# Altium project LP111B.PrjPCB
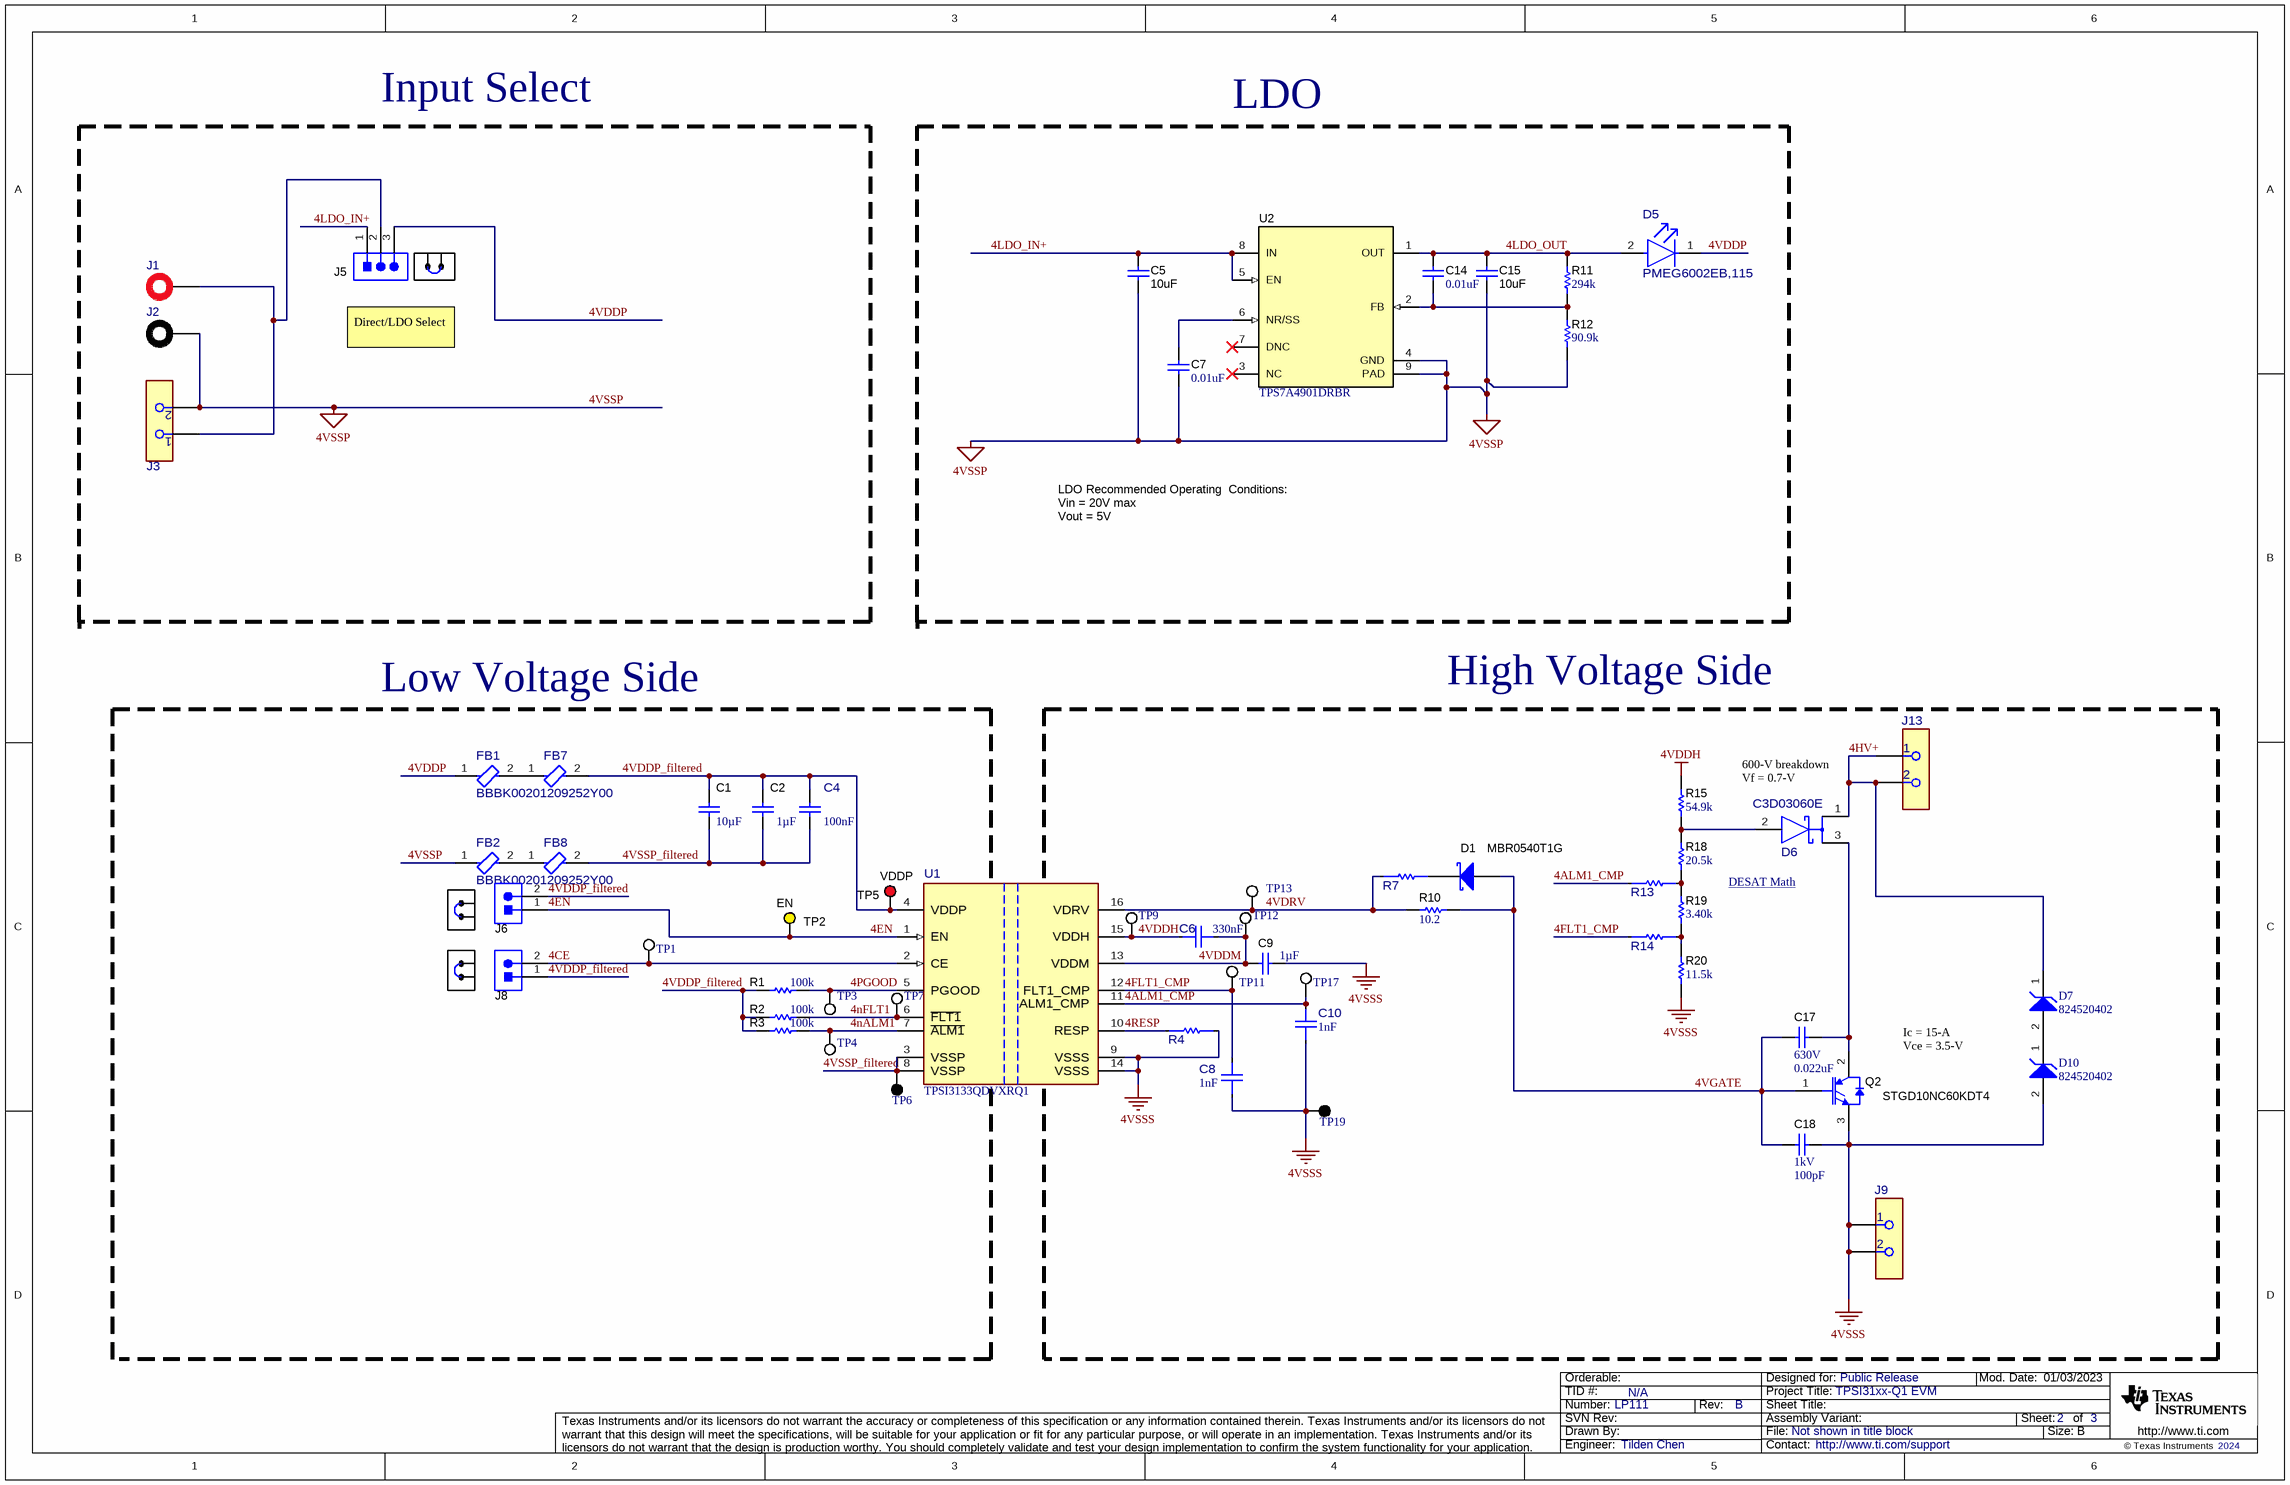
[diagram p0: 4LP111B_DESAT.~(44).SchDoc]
CopyrightYear: 2024; PCB_Layout: Tilden Chen; PCB_Rev: B; PRJ_Customer: Public Release; PRJ_Engineer: Tilden Chen; PRJ_Number: LP111; PRJ_Title: TPSI31xx-Q1 EVM; SCH_Rev: B; TechSupport: http://www.ti.com/support; TID: N/A
5 sheets, 285 parts. Net scope: global (net labels, ports and power ports of the same name join across sheets).
Board files: LP111Bv2.~(104).PcbDoc, DESAT.PcbDoc
Sheets:
  4LP111B_DESAT.~(44).SchDoc
  3LP111B_Uni-OCP_CSA.~(35).SchDoc
  2LP111B_Bi-OCP_noCSA.~(38).SchDoc
  1LP111B_Uni-OCP_noCSA.~(35).SchDoc
  LP111A_Hardware.SchDoc

## Sheet 4LP111B_DESAT.~(44).SchDoc
size 431 x 279 mm; Date: Not shown in title block; ApprovedBy: Not shown in title block; CheckedBy: Not shown in title block; Author: Not shown in title block; CompanyName: Not shown in title block; Engineer: Not shown in title block; Organization: Not shown in title block; Address1: Not shown in title block; Address2: Not shown in title block; Address3: Not shown in title block; Address4: Not shown in title block; DocumentNumber: 2; Revision: Use project parameter SCH_Rev; SheetNumber: 2; SheetTotal: 3; PageSetup: Record=PageOptions¦CenterHorizontal=True¦CenterVertical=True¦PrintScale=1.00¦XCorrection=1.00¦YCorrection=1.00¦PrintKind=0¦BorderSize=5000000¦LeftOffset=0¦BottomOffset=0¦Orientation=2¦PaperLength=1000¦PaperWidth=1000¦Scale=100¦PaperSource=15¦PrintQuality=600¦MediaType=1¦DitherType=10¦PaperKind=Letter¦PrintScaleMode=1

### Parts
C1  ValueDisplayed: 10µF  [1206_180]  (hidden comment: C1206C106J3RACAUTO)
C2  Cap_F: 1µF  [0603]  (hidden comment: GCM188R71E105KA64D)
C4  Cap_F: 100nF  [FP-C0603R104K5RAC_0603-IPC_B]  (hidden comment: C0603R104K5RAC)
C5  ValueDisplayed: 10uF  [0603]  (hidden comment: GRT188R61E106ME13D)
C6  Cap_F: 330nF  [FP-CGA3E3X7R1E334K080AB_0603-MFG]  (hidden comment: CGA3E3X7R1E334K080AB)
C7  ValueDisplayed: 0.01uF  [0402]  (hidden comment: GRM155R71E103KA01D)
C8  Cap_F: 1nF  [FP-CC0603KRX7R7BB102_0603-MFG]  (hidden comment: CC0603KRX7R7BB102)
C9  Cap_F: 1µF  [0603]  (hidden comment: GCM188R71E105KA64D)
C10  Cap_F: 1nF  [FP-CC0603KRX7R7BB102_0603-MFG]  (hidden comment: CC0603KRX7R7BB102)
C14  ValueDisplayed: 0.01uF  [0402]  (hidden comment: GRM155R71E103KA01D)
C15  ValueDisplayed: 10uF  [0603]  (hidden comment: GRT188R61E106ME13D)
C17  VDC_V: 630V  ValueDisplayed: 0.022uF  [1210_150]  (hidden comment: GRM32QR72J223KW01L)
C18  VDC_V: 1kV  ValueDisplayed: 100pF  [1206]  (hidden comment: GRM31A7U3A101JW31D)
D1  MBR0540T1G  [SOD-123]
D5  PMEG6002EB,115  [FP-PMEG6002EB,115_SOD523-MFG]
D6  C3D03060E  [FP-C3D03060E_TO-252-2-MFG]
D7  824520402  [WE-TVSP_DO-214AA_Unidirectional]
D10  824520402  [WE-TVSP_DO-214AA_Unidirectional]
FB1  BBBK00201209252Y00  [FP-BBBK00201209252Y00_0805-MFG]
FB2  BBBK00201209252Y00  [FP-BBBK00201209252Y00_0805-MFG]
FB7  BBBK00201209252Y00  [FP-BBBK00201209252Y00_0805-MFG]  (value not drawn)
FB8  BBBK00201209252Y00  [FP-BBBK00201209252Y00_0805-MFG]  (value not drawn)
J1  108-0902-001  [Cinch_108-0902-001]  (value not drawn)
J2  108-0903-001  [Cinch_108-0903-001]  (value not drawn)
J3  691250610002  [FP-691250610002_CONN_TERM_BLOCK2-MFG]  (value not drawn)
J5  PEC03SAAN  [CONN_PEC03SAAN]  (value not drawn)
J6  61300211121  [WURTH_61300211121]  (value not drawn)
J8  61300211121  [WURTH_61300211121]  (value not drawn)
J9  691250610002  [FP-691250610002_CONN_TERM_BLOCK2-MFG]  (value not drawn)
J13  691250610002  [FP-691250610002_CONN_TERM_BLOCK2-MFG]  (value not drawn)
Q2  STGD10NC60KDT4  [DPAK]
R1  ValueDisplayed: 100k  [0805_HV]  (hidden comment: ERJ-6GEYJ104V)
R2  ValueDisplayed: 100k  [0805_HV]  (hidden comment: ERJ-6GEYJ104V)
R3  ValueDisplayed: 100k  [0805_HV]  (hidden comment: ERJ-6GEYJ104V)
R4  WSL060300000ZEA9  [FP-WSL060300000ZEA9_0603-MFG]  (value not drawn)
R7  WSL060300000ZEA9  [FP-WSL060300000ZEA9_0603-MFG]  (value not drawn)
R10  ValueDisplayed: 10.2  [0805_HV]  (hidden comment: CRCW080510R2FKEA)
R11  ValueDisplayed: 294k  [0402]  (hidden comment: ERJ-2RKF2943X)
R12  ValueDisplayed: 90.9k  [0402]  (hidden comment: ERJ-2RKF9092X)
R13  WSL060300000ZEA9  [FP-WSL060300000ZEA9_0603-MFG]  (value not drawn)
R14  WSL060300000ZEA9  [FP-WSL060300000ZEA9_0603-MFG]  (value not drawn)
R15  ValueDisplayed: 54.9k  [0603]  (hidden comment: CRCW060354K9FKEA)
R18  ValueDisplayed: 20.5k  [0603]  (hidden comment: CRCW060320K5FKEA)
R19  ValueDisplayed: 3.40k  [0603]  (hidden comment: M55342K12B3E40T)
R20  ValueDisplayed: 11.5k  [0805_HV]  (hidden comment: ERJ-6ENF1152V)
SH-J1  SNT-100-BK-G  [SNT-100-BK-G]  (value not drawn)
SH-J2  SNT-100-BK-G  [SNT-100-BK-G]  (value not drawn)
SH-J3  SNT-100-BK-G  [SNT-100-BK-G]  (value not drawn)
TP1  5012  [KSTN-5012_V]  (value not drawn)
TP2  EN  [Keystone5014]
TP3  5012  [KSTN-5012_V]  (value not drawn)
TP4  5012  [KSTN-5012_V]  (value not drawn)
TP5  VDDP  [Keystone5010]
TP6  5011  [Keystone5011]  (value not drawn)
TP7  5012  [KSTN-5012_V]  (value not drawn)
TP9  5012  [KSTN-5012_V]  (value not drawn)
TP11  5012  [KSTN-5012_V]  (value not drawn)
TP12  5012  [KSTN-5012_V]  (value not drawn)
TP13  5012  [KSTN-5012_V]  (value not drawn)
TP17  5012  [KSTN-5012_V]  (value not drawn)
TP19  5011  [Keystone5011]  (value not drawn)
U1  TPSI3133QDVXRQ1  [DVX0016A-MFG]
U2  TPS7A4901DRBR  [DRB0008A]

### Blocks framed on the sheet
High Voltage Side: C6 C8-C10 C17 C18 D1 D6 D7 D10 J9 J13 Q2 R4 R7 R10 R13-R15 R18-R20 TP9 TP11-TP13 TP17 TP19

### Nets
4VDDH: C6.1 R15.2 TP9.1 U1.15(VDDH)
4VSSP: C5.2 C7.2 C15.2 FB2.1 J2.1 J3.2 R12.1 U2.4(GND) U2.9(PAD)
4VSSS: C8.1 C9.1 C10.1 C18.1 D10.2(A) J9.1 J9.2 Q2.3(E) R4.2 R20.1 TP19.1 U1.9(VSSS) U1.14(VSSS)
4ALM1_CMP: C10.2 R13.1 TP17.1 U1.11(ALM1_CMP)
4CE: J8.2 TP1.1 U1.2(CE)
4EN: J6.1 TP2.1 U1.1(EN)
4FLT1_CMP: C8.2 R14.1 TP11.1 U1.12(FLT1_CMP)
4HV+: D6.1(CATHODE) D7.1(K) J13.1 J13.2
4LDO_IN+: C5.1 J5.1 U2.5(EN) U2.8(IN)
4LDO_OUT: C14.1 C15.1 D5.2(ANODE) R11.2 U2.1(OUT)
4nALM1: R3.2 TP4.1 U1.7(~{ALM1})
4nFLT1: R2.2 TP7.1 U1.6(~{FLT1})
4PGOOD: R1.2 TP3.1 U1.5(PGOOD)
4RESP: R4.1 U1.10(RESP)
4VDDM: C6.2 C9.2 TP12.1 U1.13(VDDM)
4VDDP: D5.1(CATHODE) FB1.1 J5.3
4VDDP_filtered: C1.1 C2.1 C4.2 FB7.2 J6.2 J8.1 R1.1 R2.1 R3.1 TP5.1 U1.4(VDDP)
4VDRV: R7.1 R10.1 TP13.1 U1.16(VDRV)
4VGATE: C17.2 C18.2 D1.2(A) Q2.1(G) R10.2
4VSSP_filtered: C1.2 C2.2 C4.1 FB8.2 TP6.1 U1.3(VSSP) U1.8(VSSP)
NetC7_1: C7.1 U2.6(NR/SS)
NetC14_2: C14.2 R11.1 R12.2 U2.2(FB)
NetC17_1: C17.1 D6.3(CATHODE) Q2.2(C)
NetD1_1: D1.1(K) R7.2
NetD6_2: D6.2(ANODE) R15.1 R18.2
NetD7_2: D7.2(A) D10.1(K)
NetFB1_2: FB1.2 FB7.1
NetFB2_2: FB2.2 FB8.1
NetJ1_1: J1.1 J3.1 J5.2
NetR13_2: R13.2 R18.1 R19.2
NetR14_2: R14.2 R19.1 R20.2

Not connected (* = marked no-connect by the designer): U2 3(NC)* 7(DNC)*

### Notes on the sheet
- Input Select
- LDO
- Direct/LDO Select
- LDO Recommended Operating  Conditions:
  Vin = 20V max
  Vout = 5V
- Low Voltage Side
- (near D6) 600-V breakdown
  Vf = 0.7-V
- DESAT Math <https://www.wolframalpha.com/input?i=system+equation+calculator&assumption=%7B%22F%22%2C+%22SolveSystemOf3EquationsCalculator%22%2C+%22equation1%22%7D+-%3E%2217*%28a%2F%28a%2Bb%2Bc%29%29%3D1.02%22&assumption=%22FSelect%22+-%3E+%7B%7B%22SolveSystemOf3EquationsCalculator%22%7D%2C+%22dflt%22%7D&assumption=%7B%22F%22%2C+%22SolveSystemOf3EquationsCalculator%22%2C+%22equation2%22%7D+-%3E%224.2*%28a%2F%28a%2Bb%29%29%3D1.33%22&assumption=%7B%22F%22%2C+%22SolveSystemOf3EquationsCalculator%22%2C+%22equation3%22%7D+-%3E%22c%3D154e3%22>
- Ic = 15-A
  Vce = 3.5-V

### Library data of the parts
C1 = CMP-0081062-1: CAP, CERM, 10 µF, 25 V,+/- 5%, X7R, AEC-Q200 Grade 1, 1206; Manufacturer: Kemet; TaMin_C: -55°C; Polarized: N; SizeAreaWB_mm2: 10.92; U/M: EA; Value: 10uF; TaMax_C: 125°C; SizeZ_mm: 1.8; SizeX_mm: 3.2; SizeY_mm: 1.6; Value2: 25V; SizeArea_mm2: 5.12; AEC Qualified: Y; AEC Grade: 1; AEC Category: Q200
C2 C9 = CMP-0007139-4: CAP, CERM, 1 uF, 25 V, +/- 10%, X7R, AEC-Q200 Grade 1, 0603; Manufacturer: MuRata; TaMin_C: -55°C; Polarized: N; SizeAreaWB_mm2: 4.68; Value1: Unknown; U/M: EA; Value: 1uF; TaMax_C: 125°C; SizeZ_mm: 1; SizeX_mm: 1.6; SizeY_mm: 0.8; Value2: 25V; SizeArea_mm2: 1.28; AEC Qualified: Y; AEC Category: Q200
C4 = CMP-0087061-2: CAP CER 0.1UF 50V X7R 0603; Manufacturer: Kemet; TempCo: 15%; SizeZ_mm: 0.87mm; Tolerance_%: 10%; AEC Qualified: No; Symbol Name: SYM-C0603R104K5RAC
C5 C15 = CMP-0007501-1: CAP, CERM, 10 uF, 25 V, +/- 20%, X5R, 0603; Manufacturer: MuRata; TaMin_C: -55°C; Polarized: N; SizeAreaWB_mm2: 4.68; Value1: Unknown; U/M: EA; Value: 10uF; TaMax_C: 85°C; SizeZ_mm: 1; SizeX_mm: 1.6; SizeY_mm: 0.8; Value2: 25V; SizeArea_mm2: 1.28; Cap_F: 10µF; AEC Category: Q200
C6 = CMP-0030960-1: Cap Ceramic 330nF 25V X7R 10% Pad SMD 0603 +125°C Automotive T/R; Manufacturer: TDK; AEC Grade: Grade 1; AEC Qualified: Yes; SizeZ_mm: 1.1mm; TempCo: 0.15; Tolerance_%: 0.1%
C7 C14 = CMP-0006658-2: CAP, CERM, 0.01 uF, 25 V, +/- 10%, X7R, 0402; Manufacturer: MuRata; TaMin_C: -55°C; Polarized: N; SizeAreaWB_mm2: 3; Value1: Unknown; U/M: EA; Value: 0.01uF; TaMax_C: 125°C; SizeZ_mm: 0.6; SizeX_mm: 1; SizeY_mm: 0.5; Value2: 25V; Cap_F: 10nF; AEC Category: Q200
C8 C10 = CMP-0094870-1: 1000 pF ±10% 16V Ceramic Capacitor X7R 0603 (1608 Metric); Manufacturer: YAGEO; AEC Qualified: No; Value: 1nF; ValueDisplayed: 1.0 nF; TempCo: 15%; SizeZ_mm: 0.9mm
C17 = CMP-0009248-2: CAP, CERM, 0.022 uF, 630 V, +/- 10%, X7R, 1210; Manufacturer: MuRata; TaMin_C: -55°C; Polarized: N; SizeAreaWB_mm2: 14.7; Value1: Unknown; U/M: EA; TaMax_C: 125°C; SizeZ_mm: 1.5; SizeX_mm: 3.2; SizeY_mm: 2.5; Cap_Case: 1210; SizeArea_mm2: 8; Cap_F: 22nF; AEC Category: Q200
C18 = CMP-0008897-2: CAP, CERM, 100 pF, 1000 V, +/- 5%, U2J, 1206; Manufacturer: MuRata; TaMin_C: -55°C; Polarized: N; SizeAreaWB_mm2: 10.92; Value1: Unknown; U/M: EA; Value: 100pF; TaMax_C: 125°C; SizeZ_mm: 1.35; SizeX_mm: 3.2; SizeY_mm: 1.6; Value2: 1000V; SizeArea_mm2: 5.12; AEC Category: Q200
D1 = CMP-0028526-2: Diode, Schottky, 40 V, 0.5 A, SOD-123; Manufacturer: ON Semiconductor; Green_REACh: Passed; SizeY_mm: 1.7; Io_A: 500mA; SizeArea_mm2: 6.545; RJC_CperW: 118; Green_Lifecycle: Active; Vr_V: 40V; Vf_V: 510mV; TJmax_C: 150°C; AEC Category: Q101; SizeAreaWB_mm2: 13.095; Value1: 0.5A; SizeZ_mm: 1.35; SizeX_mm: 3.85; Value2: 0.51V; Value: 40V
D5 = CMP-0087203-1: DIODE SCHOTTKY 60V 200MA SOD523; Manufacturer: Nexperia; Symbol Name: SYM-PMEG6002EB,115; SizeZ_mm: 0.65mm; AEC Qualified: Yes; TJmax_C: 150°C
D6 = CMP-0092653-1: Diode Silicon Carbide Schottky 600 V 11A (DC) Surface Mount TO-252-2; Manufacturer: Cree; Cap_F: 166pF; Vr_V: 600V; Peak Reverse Current: 4uA; AEC Grade: Grade 0; AEC Qualified: Yes; Standoff Height: 0mm; SizeZ_mm: 2.543mm; TJmax_C: 175°C; Max Surge Forward Current: 26A
D7 D10 = CMP-03913-133963852-1: 824520402 Tvs Diode, Unidir, 400V, Smb Rohs Compliant: Yes; Leakage Current: 1µA
FB1 FB2 FB7 FB8 = CMP-0124406-1: 2.5 kOhms @ 100 MHz 1 Signal Line Ferrite Bead 0805 (2012 Metric) 200mA 700mOhm; Manufacturer: Pulse Electronics; DCR_ohm: 0.7; SizeZ_mm: 1.1mm; AEC Qualified: No; Impedance At Frequency: 2500Ω @ 100MHz; Tolerance_%: 25%
J1 = CMP-0079575-1: Banana Jack Insul Nylon Red, TH; Manufacturer: Cinch Connectivity; Gender: Female; Current_A: 15A; Green_REACh: Incomplete; ContactFinish: Tin; Green_Lifecycle: Active
J2 = CMP-0079574-1: Banana Jack Insul Nylon Black, TH; Manufacturer: Cinch Connectivity; Gender: Female; Current_A: 15A; Green_REACh: Incomplete; ContactFinish: Tin; Green_Lifecycle: Active
J3 J9 J13 = CMP-0093233-2: Manufacturer: Wurth Electronics; SizeZ_mm: 21.6mm; Min Wire Gauge: 30; DUT-Pitch_mm: 6.35mm; Is Female: yes; Row_Count: 1; Voltage_V: 450V; AEC Qualified: No; Max Wire Gauge: 10; Conn Gender: Female; Current_A: 32A; ContactFinish: Zinc; Conn Orientation: Horizontal
J5 = CMP-0002338-1: Header, 100mil, 3x1, Tin, TH; Manufacturer: Sullins Connector Solutions; CNHeader: TRUE; Current_A: 3A; Green_Lifecycle: Not Set; Shrouded: N; Gender: Male; Green_REACh: Incomplete; Voltage_V: 1.8kV; Row_Count: 1; Pitch_mm: 2.54; CT: FALSE; Cert_UL: Y
J6 J8 = CMP-0054794-2: Header, 2.54 mm, 2x1, Gold, TH; Manufacturer: Wurth Elektronik; Shrouded: N; Gender: Male; Green_REACh: Passed; Pitch_mm: 2.54; Green_Lifecycle: Active; Row_Count: 1; Cert_UL: Y
Q2 = CMP-0000528-4: Transistor, IGBT, 600 V, 20 A, DPAK; Manufacturer: STMicroelectronics; Value: 600 V; AEC Qualified: N; Value1: 20 A; IcRated_A: 20A; SizeY_mm: 6.54; AEC Category: Q101; SizeX_mm: 9.91; SizeZ_mm: 2.29; NPN: 0; TaMin_C: -55°C; Vcesat1_V: 2.2V; Vceo_V: 600V; TaMax_C: 150°C; SizeAreaWB_mm2: 101.7114; SizeArea_mm2: 64.8114
R1-R3 = CMP-0020622-3: RES, 100 k, 5%, 0.125 W, AEC-Q200 Grade 0, 0805; Manufacturer: Panasonic; Power_W: 125mW; TempCo: 200 ppm/C; Value: 100k; EIA_Code: E24; SizeX_mm: 2; SizeY_mm: 1.25; SizeZ_mm: 1.45; Value2: 0.125W; SizeArea_mm2: 2.5; AEC Qualified: Y; VDC_V: 150V; AEC Category: Q200; AEC Grade: 0; SizeAreaWB_mm2: 6.75
R4 R7 R13 R14 = CMP-0031931-1: 0 Ohms Jumper Chip Resistor 0603 (1608 Metric) Metal Element; Manufacturer: Vishay; AEC Qualified: No; Res_ohm: 0; SizeZ_mm: 0.457mm; TempCo: 3900ppm/°C; Value: 0
R10 = CMP-0020848-3: RES, 10.2, 1%, 0.125 W, AEC-Q200 Grade 0, 0805; Manufacturer: Vishay-Dale; Power_W: 125mW; TempCo: 100 ppm/C; Value_Code: 10R2; Value: 10.2; EIA_Code: E96; SizeX_mm: 2; SizeY_mm: 1.25; SizeZ_mm: 1.45; Value2: 0.125W; SizeArea_mm2: 2.5; AEC Qualified: Y; VDC_V: 150V; AEC Category: Q200; AEC Grade: 0
R11 = CMP-0026693-1: RES, 294 k, 1%, 0.1 W, AEC-Q200 Grade 0, 0402; Manufacturer: Panasonic; Power_W: 100mW; TempCo: 100 ppm/C; U/M: EA; Value: 294k; EIA_Code: E96; SizeX_mm: 1; SizeY_mm: 0.5; SizeZ_mm: 0.6; Value2: 0.1W; AEC Qualified: Y; VDC_V: 50V; AEC Grade: 0; AEC Category: Q200
R12 = CMP-0026711-1: RES, 90.9 k, 1%, 0.1 W, AEC-Q200 Grade 0, 0402; Manufacturer: Panasonic; Power_W: 100mW; TempCo: 100 ppm/C; Value_Code: 90k9; U/M: EA; Value: 90.9k; EIA_Code: E96; SizeX_mm: 1; SizeY_mm: 0.5; SizeZ_mm: 0.6; Value2: 0.1W; AEC Qualified: Y; VDC_V: 50V; AEC Grade: 0; AEC Category: Q200
R15 = CMP-0022494-4: RES, 54.9 k, 1%, 0.1 W, AEC-Q200 Grade 0, 0603; Manufacturer: Vishay-Dale; Power_W: 100mW; TempCo: 100 ppm/C; Value_Code: 54k9; Value: 54.9k; EIA_Code: E96; SizeX_mm: 1.6; SizeY_mm: 0.8; SizeZ_mm: 1; Value2: 0.1W; SizeArea_mm2: 1.28; AEC Qualified: Y; VDC_V: 75V; AEC Category: Q200; AEC Grade: 0
R18 = CMP-0022205-4: RES, 20.5 k, 1%, 0.1 W, AEC-Q200 Grade 0, 0603; Manufacturer: Vishay-Dale; Power_W: 100mW; TempCo: 100 ppm/C; Value_Code: 20k5; Value: 20.5k; EIA_Code: E96; SizeX_mm: 1.6; SizeY_mm: 0.8; SizeZ_mm: 1; Value2: 0.1W; SizeArea_mm2: 1.28; AEC Qualified: Y; VDC_V: 75V; AEC Category: Q200; AEC Grade: 0
R19 = CMP-0080491-1: RES, 3.40 k, 1%, 0.1 W, 0603; Manufacturer: TT Electronics/IRC; Power_W: 100mW; TempCo: 100 ppm/C; SizeAreaWB_mm2: 4.68; Value_Code: 3k40; Value: 3.40k; EIA_Code: E96; Res_ohm: 3.4k; SizeX_mm: 1.6; SizeY_mm: 0.8; SizeZ_mm: 1; Value2: 0.1W; SizeArea_mm2: 1.28; AEC Qualified: N; AEC Category: Q200
R20 = CMP-0021540-3: RES, 11.5 k, 1%, 0.125 W, AEC-Q200 Grade 0, 0805; Manufacturer: Panasonic; Power_W: 125mW; TempCo: 100 ppm/C; Value_Code: 11k5; Value: 11.5k; EIA_Code: E96; SizeX_mm: 2; SizeY_mm: 1.25; SizeZ_mm: 1.45; Value2: 0.125W; SizeArea_mm2: 2.5; AEC Qualified: Y; AEC Category: Q200; AEC Grade: 0; SizeAreaWB_mm2: 6.75
SH-J1-SH-J3 = CMP-0003623-3: Shunt, 100mil, Gold plated, Black; Alternate PartNumber: 969102-0000-DA; Manufacturer: Samtec; Alternate Manufacturer: 3M; Value: 1x2
TP1 TP3 TP4 TP7 TP9 TP11-TP13 TP17 = CMP-1672-00004-4: Test Point, White, Through Hole, RoHS, Bulk; Manufacturer: Keystone
TP2 = CMP-0055151-2: Test Point, Multipurpose, Yellow, TH; Manufacturer: Keystone Electronics; CNHeader: FALSE; Green_Lifecycle: Active; Green_REACh: Passed; ContactFinish: Silver; CT: TRUE
TP5 = CMP-0055147-2: Test Point, Multipurpose, Red, TH; Manufacturer: Keystone Electronics; CNHeader: FALSE; Green_Lifecycle: Active; Green_REACh: Passed; ContactFinish: Silver; CT: TRUE
TP6 TP19 = CMP-0055148-2: Test Point, Multipurpose, Black, TH; Manufacturer: Keystone Electronics; CNHeader: FALSE; ContactFinish: Silver; Green_REACh: Passed; Green_Lifecycle: Active; CT: TRUE
U1 = CMP-0123884-1: Manufacturer: Texas Instruments; SizeZ_mm: 2.6mm; Standoff Height: 0.14mm
U2 = CMP-0073868-3: Vin 3V to 36V, 150mA, Ultra-Low-Noise, High-PSRR Low-Dropout (LDO) Linear Regulator, DRB0008A (VSON-8); Manufacturer: Texas Instruments; Alternate PartNumber: TPS7A4901DRBT; AEC Category: Q200; CompType: IC; SizeZ_mm: 1.0; Rating: Catalog; SizeAreaWB_mm2: 16.0; SizeX_mm: 3.0; SizeArea_mm2: 9.0; AEC Qualified: N

## Sheet 3LP111B_Uni-OCP_CSA.~(35).SchDoc
size 431 x 279 mm; Date: Not shown in title block; ApprovedBy: Not shown in title block; CheckedBy: Not shown in title block; Author: Not shown in title block; CompanyName: Not shown in title block; Engineer: Not shown in title block; Organization: Not shown in title block; Address1: Not shown in title block; Address2: Not shown in title block; Address3: Not shown in title block; Address4: Not shown in title block; DocumentNumber: 1; Revision: Use project parameter SCH_Rev; SheetNumber: 1; SheetTotal: 2; PageSetup: Record=PageOptions¦CenterHorizontal=True¦CenterVertical=True¦PrintScale=1.00¦XCorrection=1.00¦YCorrection=1.00¦PrintKind=0¦BorderSize=5000000¦LeftOffset=0¦BottomOffset=0¦Orientation=2¦PaperLength=1000¦PaperWidth=1000¦Scale=100¦PaperSource=15¦PrintQuality=600¦MediaType=1¦DitherType=10¦PaperKind=Letter¦PrintScaleMode=1
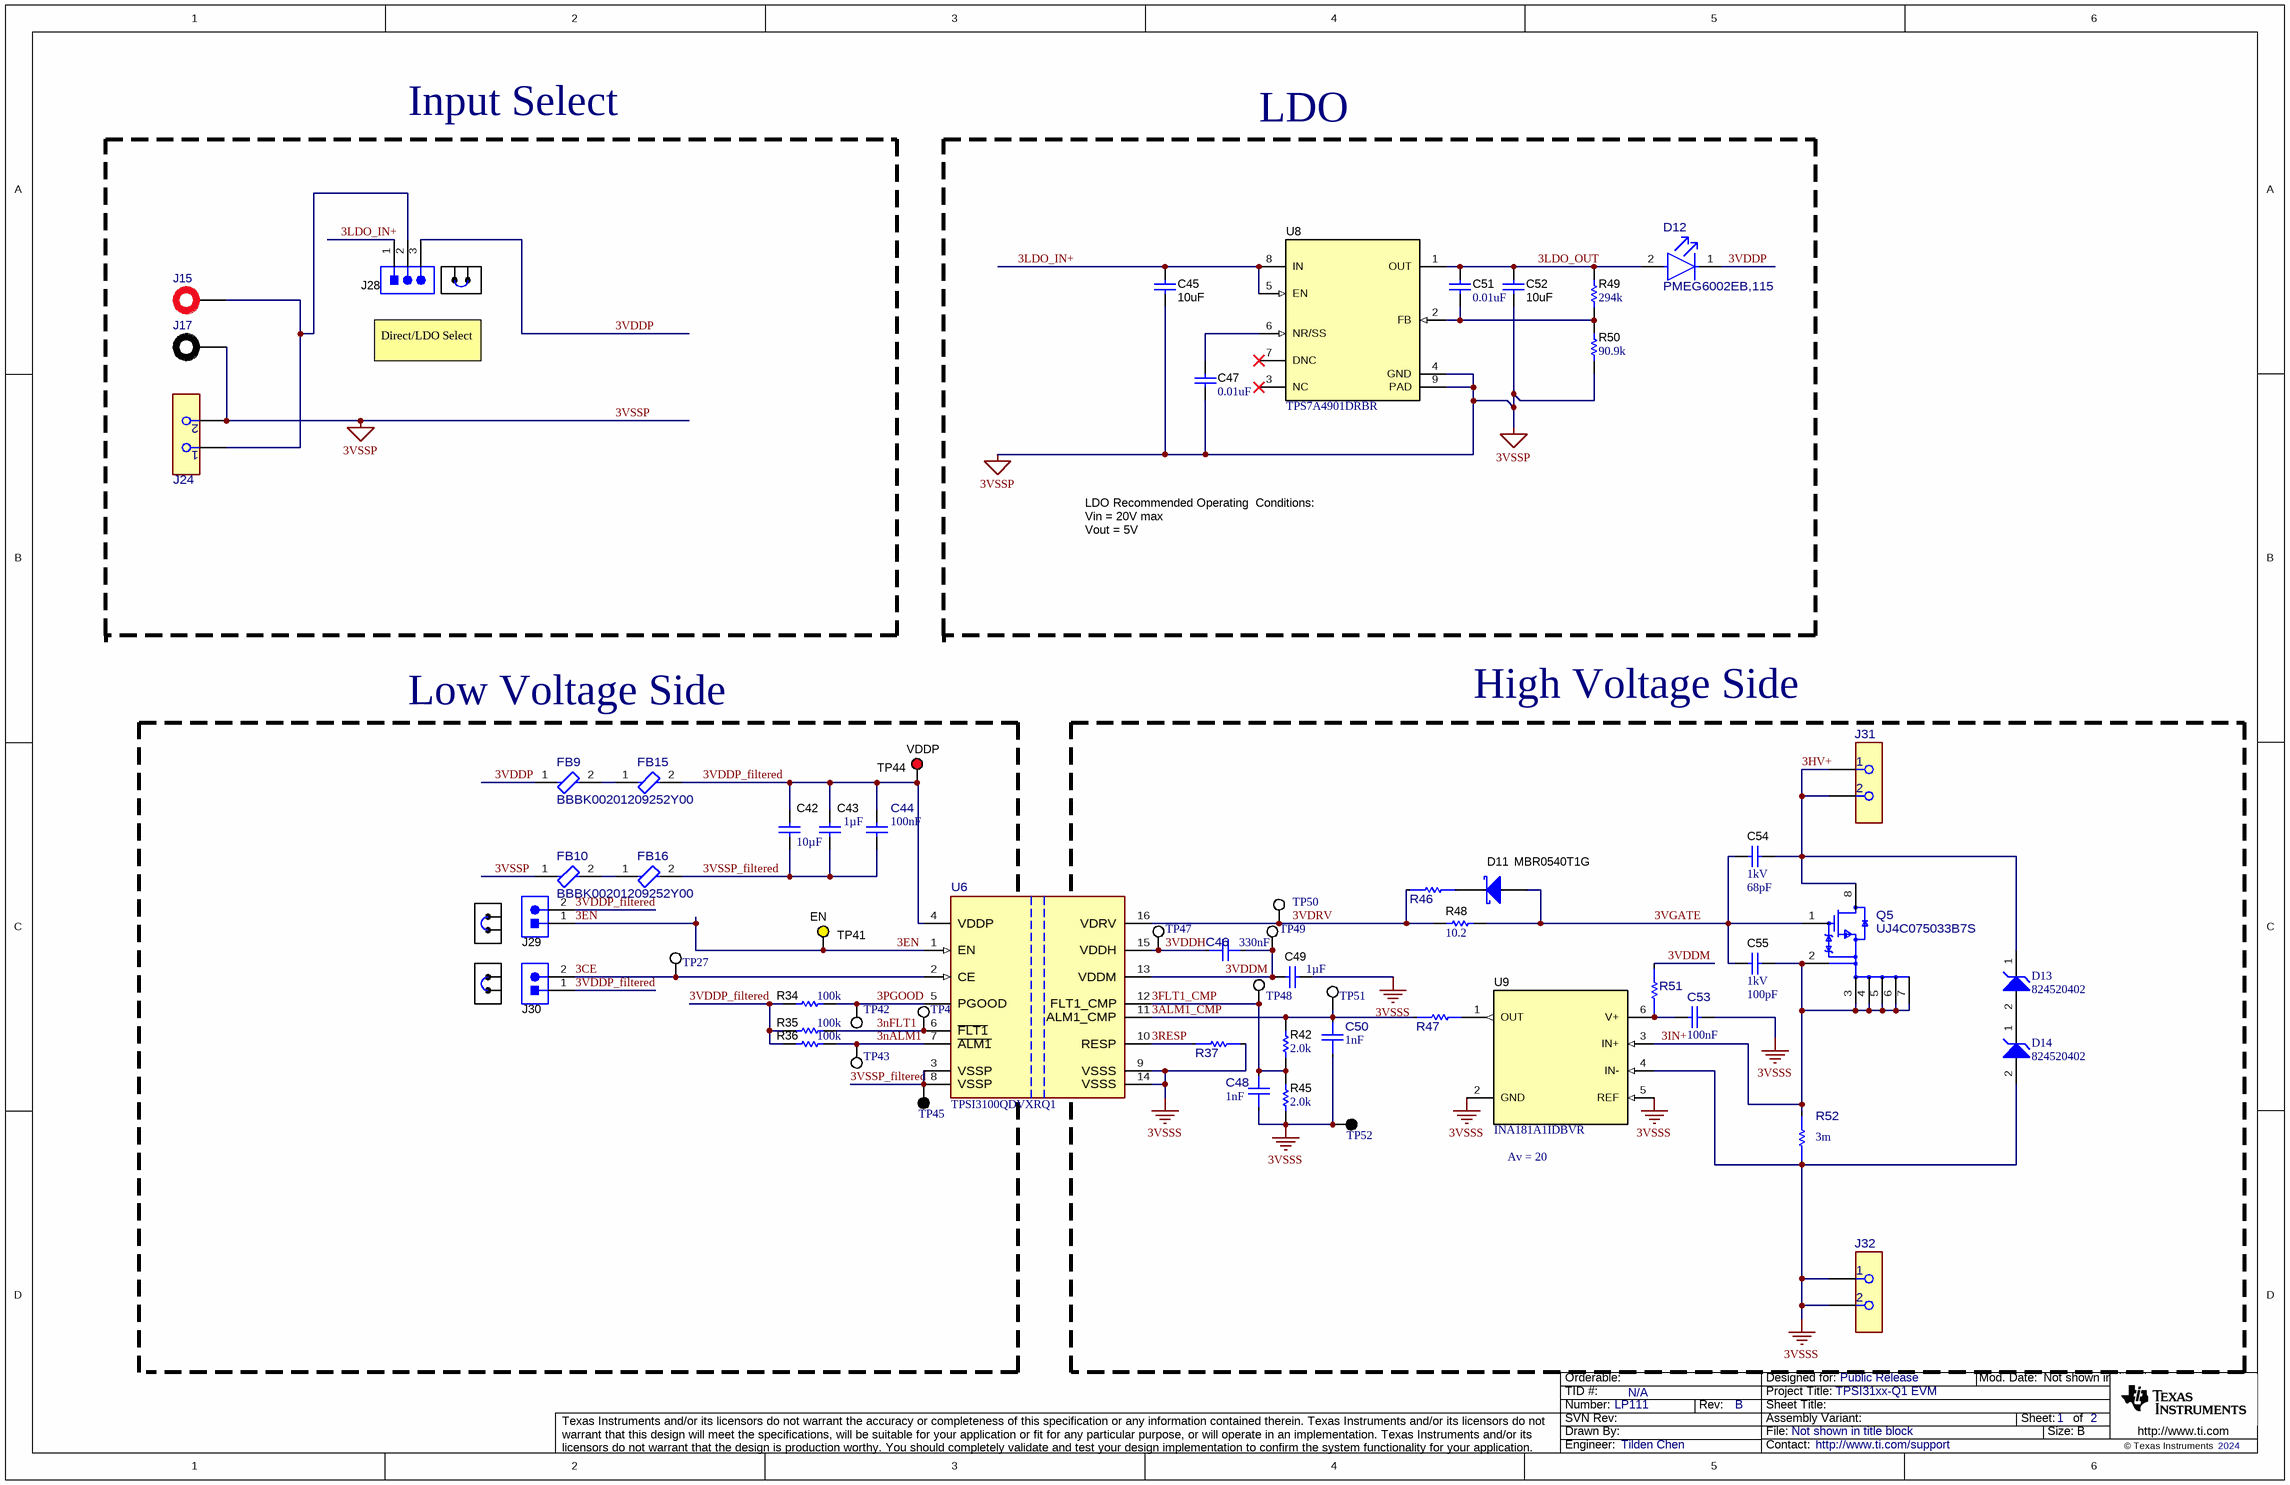
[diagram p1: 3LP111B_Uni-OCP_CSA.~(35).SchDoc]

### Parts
C42  ValueDisplayed: 10µF  [1206_180]  (hidden comment: C1206C106J3RACAUTO)
C43  Cap_F: 1µF  [0603]  (hidden comment: GCM188R71E105KA64D)
C44  Cap_F: 100nF  [FP-C0603R104K5RAC_0603-IPC_B]  (hidden comment: C0603R104K5RAC)
C45  ValueDisplayed: 10uF  [0603]  (hidden comment: GRT188R61E106ME13D)
C46  Cap_F: 330nF  [FP-CGA3E3X7R1E334K080AB_0603-MFG]  (hidden comment: CGA3E3X7R1E334K080AB)
C47  ValueDisplayed: 0.01uF  [0402]  (hidden comment: GRM155R71E103KA01D)
C48  Cap_F: 1nF  [FP-CC0603KRX7R7BB102_0603-MFG]  (hidden comment: CC0603KRX7R7BB102)
C49  Cap_F: 1µF  [0603]  (hidden comment: GCM188R71E105KA64D)
C50  Cap_F: 1nF  [FP-CC0603KRX7R7BB102_0603-MFG]  (hidden comment: CC0603KRX7R7BB102)
C51  ValueDisplayed: 0.01uF  [0402]  (hidden comment: GRM155R71E103KA01D)
C52  ValueDisplayed: 10uF  [0603]  (hidden comment: GRT188R61E106ME13D)
C53  Cap_F: 100nF  [FP-C0603R104K5RAC_0603-IPC_B]  (hidden comment: C0603R104K5RAC)
C54  VDC_V: 1kV  ValueDisplayed: 68pF  [1206]  (hidden comment: GRM31A7U3A680JW31D)
C55  VDC_V: 1kV  ValueDisplayed: 100pF  [1206]  (hidden comment: GRM31A7U3A101JW31D)
D11  MBR0540T1G  [SOD-123]
D12  PMEG6002EB,115  [FP-PMEG6002EB,115_SOD523-MFG]
D13  824520402  [WE-TVSP_DO-214AA_Unidirectional]
D14  824520402  [WE-TVSP_DO-214AA_Unidirectional]
FB9  BBBK00201209252Y00  [FP-BBBK00201209252Y00_0805-MFG]
FB10  BBBK00201209252Y00  [FP-BBBK00201209252Y00_0805-MFG]
FB15  BBBK00201209252Y00  [FP-BBBK00201209252Y00_0805-MFG]  (value not drawn)
FB16  BBBK00201209252Y00  [FP-BBBK00201209252Y00_0805-MFG]  (value not drawn)
J15  108-0902-001  [Cinch_108-0902-001]  (value not drawn)
J17  108-0903-001  [Cinch_108-0903-001]  (value not drawn)
J24  691250610002  [FP-691250610002_CONN_TERM_BLOCK2-MFG]  (value not drawn)
J28  PEC03SAAN  [CONN_PEC03SAAN]  (value not drawn)
J29  61300211121  [WURTH_61300211121]  (value not drawn)
J30  61300211121  [WURTH_61300211121]  (value not drawn)
J31  691250610002  [FP-691250610002_CONN_TERM_BLOCK2-MFG]  (value not drawn)
J32  691250610002  [FP-691250610002_CONN_TERM_BLOCK2-MFG]  (value not drawn)
Q5  UJ4C075033B7S  [FP-UJ4C075033B7S_D2PAK7-MFG]
R34  ValueDisplayed: 100k  [0805_HV]  (hidden comment: ERJ-6GEYJ104V)
R35  ValueDisplayed: 100k  [0805_HV]  (hidden comment: ERJ-6GEYJ104V)
R36  ValueDisplayed: 100k  [0805_HV]  (hidden comment: ERJ-6GEYJ104V)
R37  WSL060300000ZEA9  [FP-WSL060300000ZEA9_0603-MFG]  (value not drawn)
R42  ValueDisplayed: 2.0k  [0603]  (hidden comment: RC0603JR-072KL)
R45  ValueDisplayed: 2.0k  [0603]  (hidden comment: RC0603JR-072KL)
R46  WSL060300000ZEA9  [FP-WSL060300000ZEA9_0603-MFG]  (value not drawn)
R47  RC0805FR-070RL  [FP-RC0805FR-070RL_0805-MFG]  (value not drawn)
R48  ValueDisplayed: 10.2  [0805_HV]  (hidden comment: CRCW080510R2FKEA)
R49  ValueDisplayed: 294k  [0402]  (hidden comment: ERJ-2RKF2943X)
R50  ValueDisplayed: 90.9k  [0402]  (hidden comment: ERJ-2RKF9092X)
R51  WSL060300000ZEA9  [FP-WSL060300000ZEA9_0603-MFG]  (value not drawn)
R52  value 3m  [FP-ERJ-MS4SF3M0U_2512-MFG]  (hidden comment: ERJ-MS4SF3M0U)
SH-J10  SNT-100-BK-G  [SNT-100-BK-G]  (value not drawn)
SH-J11  SNT-100-BK-G  [SNT-100-BK-G]  (value not drawn)
SH-J12  SNT-100-BK-G  [SNT-100-BK-G]  (value not drawn)
TP27  5012  [KSTN-5012_V]  (value not drawn)
TP41  EN  [Keystone5014]
TP42  5012  [KSTN-5012_V]  (value not drawn)
TP43  5012  [KSTN-5012_V]  (value not drawn)
TP44  VDDP  [Keystone5010]
TP45  5011  [Keystone5011]  (value not drawn)
TP46  5012  [KSTN-5012_V]  (value not drawn)
TP47  5012  [KSTN-5012_V]  (value not drawn)
TP48  5012  [KSTN-5012_V]  (value not drawn)
TP49  5012  [KSTN-5012_V]  (value not drawn)
TP50  5012  [KSTN-5012_V]  (value not drawn)
TP51  5012  [KSTN-5012_V]  (value not drawn)
TP52  5011  [Keystone5011]  (value not drawn)
U6  TPSI3100QDVXRQ1  [DVX0016A-MFG]
U8  TPS7A4901DRBR  [DRB0008A]
U9  INA181A1IDBVR  [DBV0006A_N]

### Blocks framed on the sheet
High Voltage Side: C46 C48-C50 C53-C55 D11 D13 D14 J31 J32 Q5 R37 R42 R45-R48 R51 R52 TP47-TP52 U9

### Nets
3VSSP: C45.2 C47.2 C52.2 FB10.1 J17.1 J24.2 R50.1 U8.4(GND) U8.9(PAD)
3VSSS: C48.1 C49.1 C50.1 C53.2 D14.2(A) J32.1 J32.2 R37.2 R45.1 R52.1 TP52.1 U6.9(VSSS) U6.14(VSSS) U9.2(GND) U9.4(IN-) U9.5(REF)
3ALM1_CMP: C50.2 R42.2 R47.1 TP51.1 U6.11(ALM1_CMP)
3CE: J30.2 TP27.1 U6.2(CE)
3EN: J29.1 TP41.1 U6.1(EN)
3FLT1_CMP: C48.2 R42.1 R45.2 TP48.1 U6.12(FLT1_CMP)
3HV+: C54.1 D13.1(K) J31.1 J31.2 Q5.8(D)
3IN+: C55.1 Q5.2(KS) Q5.3(S) Q5.4(S) Q5.5(S) Q5.6(S) Q5.7(S) R52.2 U9.3(IN+)
3LDO_IN+: C45.1 J28.1 U8.5(EN) U8.8(IN)
3LDO_OUT: C51.1 C52.1 D12.2(ANODE) R49.2 U8.1(OUT)
3nALM1: R36.2 TP43.1 U6.7(~{ALM1})
3nFLT1: R35.2 TP46.1 U6.6(~{FLT1})
3PGOOD: R34.2 TP42.1 U6.5(PGOOD)
3RESP: R37.1 U6.10(RESP)
3VDDH: C46.1 TP47.1 U6.15(VDDH)
3VDDM: C46.2 C49.2 R51.2 TP49.1 U6.13(VDDM)
3VDDP: D12.1(CATHODE) FB9.1 J28.3
3VDDP_filtered: C42.1 C43.1 C44.2 FB15.2 J29.2 J30.1 R34.1 R35.1 R36.1 TP44.1 U6.4(VDDP)
3VDRV: R46.1 R48.1 TP50.1 U6.16(VDRV)
3VGATE: C54.2 C55.2 D11.2(A) Q5.1(G) R48.2
3VSSP_filtered: C42.2 C43.2 C44.1 FB16.2 TP45.1 U6.3(VSSP) U6.8(VSSP)
NetC47_1: C47.1 U8.6(NR/SS)
NetC51_2: C51.2 R49.1 R50.2 U8.2(FB)
NetC53_1: C53.1 R51.1 U9.6(V+)
NetD11_1: D11.1(K) R46.2
NetD13_2: D13.2(A) D14.1(K)
NetFB9_2: FB9.2 FB15.1
NetFB10_2: FB10.2 FB16.1
NetJ15_1: J15.1 J24.1 J28.2
NetR47_2: R47.2 U9.1(OUT)

Not connected (* = marked no-connect by the designer): U8 3(NC)* 7(DNC)*

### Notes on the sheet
- Input Select
- LDO
- Direct/LDO Select
- LDO Recommended Operating  Conditions:
  Vin = 20V max
  Vout = 5V
- Low Voltage Side
- Av = 20

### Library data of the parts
C42 = CMP-0081062-1: as C1 on sheet 4LP111B_DESAT.~(44)
C43 C49 = CMP-0007139-4: as C2 on sheet 4LP111B_DESAT.~(44)
C44 C53 = CMP-0087061-2: as C4 on sheet 4LP111B_DESAT.~(44)
C45 C52 = CMP-0007501-1: as C5 on sheet 4LP111B_DESAT.~(44)
C46 = CMP-0030960-1: as C6 on sheet 4LP111B_DESAT.~(44)
C47 C51 = CMP-0006658-2: as C7 on sheet 4LP111B_DESAT.~(44)
C48 C50 = CMP-0094870-1: as C8 on sheet 4LP111B_DESAT.~(44)
C54 = CMP-0008902-2: CAP, CERM, 68 pF, 1000 V, +/- 5%, U2J, 1206; Manufacturer: MuRata; TaMin_C: -55°C; Polarized: N; SizeAreaWB_mm2: 10.92; Value1: Unknown; U/M: EA; Value: 68pF; TaMax_C: 125°C; SizeZ_mm: 1.35; SizeX_mm: 3.2; SizeY_mm: 1.6; Value2: 1000V; SizeArea_mm2: 5.12; AEC Category: Q200
C55 = CMP-0008897-2: as C18 on sheet 4LP111B_DESAT.~(44)
D11 = CMP-0028526-2: as D1 on sheet 4LP111B_DESAT.~(44)
D12 = CMP-0087203-1: as D5 on sheet 4LP111B_DESAT.~(44)
D13 D14 = CMP-03913-133963852-1: as D7 on sheet 4LP111B_DESAT.~(44)
FB9 FB10 FB15 FB16 = CMP-0124406-1: as FB1 on sheet 4LP111B_DESAT.~(44)
J15 = CMP-0079575-1: as J1 on sheet 4LP111B_DESAT.~(44)
J17 = CMP-0079574-1: as J2 on sheet 4LP111B_DESAT.~(44)
J24 J31 J32 = CMP-0093233-2: as J3 on sheet 4LP111B_DESAT.~(44)
J28 = CMP-0002338-1: as J5 on sheet 4LP111B_DESAT.~(44)
J29 J30 = CMP-0054794-2: as J6 on sheet 4LP111B_DESAT.~(44)
Q5 = CMP-0120465-1: MOSFET N-Channel 750 V 44A (Tc) 197W (Tc) Surface Mount D2PAK-7; Manufacturer: Qorvo; AEC Qualified: No; QgTyp_nC: 37.8nC @ 15V; Rdson45_ohm: 33m; SizeZ_mm: 4.81mm; VdsMax_V: 1.42V; Vgs_V: 20V; ChMode: False; Drain To Source Breakdown Voltage: 750V; Input Capacitace At Vds: 1400pF @ 400V; Number Of Channels: 1; Pulse Drain Current: 140A; Reverse Recovery Charge: 62nC; Reverse Recovery Time: 11.2ns; Standoff Height: 0mm; Threshold Vgs Max: 6V; Threshold Vgs Min: 4V; TJmax_C: +175°C; Turn Off Delay Time: 157ns; Turn On Delay Time: 11ns; Typ Forward Diode Voltage: 1.26V
R34-R36 = CMP-0020622-3: as R1 on sheet 4LP111B_DESAT.~(44)
R37 R46 R51 = CMP-0031931-1: as R4 on sheet 4LP111B_DESAT.~(44)
R42 R45 = CMP-0025909-5: RES, 2.0 k, 5%, 0.1 W, 0603; Manufacturer: Yageo; Power_W: 100mW; TempCo: 100 ppm/C; Value_Code: 2k00; Value: 2.0k; EIA_Code: E24; Res_ohm: 2k; SizeX_mm: 1.6; SizeY_mm: 0.8; SizeZ_mm: 1; Value2: 0.1W; SizeArea_mm2: 1.28; AEC Qualified: N; VDC_V: 75V; AEC Category: Q200; SizeAreaWB_mm2: 4.68
R47 = CMP-0092692-1: RES SMD 0 OHM JUMPER 1/8W 0805; Manufacturer: Yageo; Res_ohm: 0; AEC Qualified: No; SizeZ_mm: 0.6mm; Value: 0; VDC_V: 150V; Power_W: 125mW; Tolerance_%: 1%
R48 = CMP-0020848-3: as R10 on sheet 4LP111B_DESAT.~(44)
R49 = CMP-0026693-1: as R11 on sheet 4LP111B_DESAT.~(44)
R50 = CMP-0026711-1: as R12 on sheet 4LP111B_DESAT.~(44)
R52 = CMP-0120455-1: Res Metal Plate 2512 0.003 Ohm 1% 3W ±75ppm/C Pad SMD Automotive T/R; Manufacturer: Panasonic; AEC Grade: Grade 0; AEC Qualified: Yes; SizeZ_mm: 1.35mm; TempCo: 75ppm/°C
SH-J10-SH-J12 = CMP-0003623-3: as SH-J1 on sheet 4LP111B_DESAT.~(44)
TP27 TP42 TP43 TP46-TP51 = CMP-1672-00004-4: as TP1 on sheet 4LP111B_DESAT.~(44)
TP41 = CMP-0055151-2: as TP2 on sheet 4LP111B_DESAT.~(44)
TP44 = CMP-0055147-2: as TP5 on sheet 4LP111B_DESAT.~(44)
TP45 TP52 = CMP-0055148-2: as TP6 on sheet 4LP111B_DESAT.~(44)
U6 = CMP-0029491-2: Automotive Reinforced Isolated Switch Driver with Integrated 15-V Gate Supply and Fault/Alarm Indicators; Manufacturer: Texas Instruments; SizeZ_mm: 2.6mm; AEC Qualified: Yes; AEC Grade: Grade 1; Max Supply Voltage: 5.5V; Min Supply Voltage: 4.5V; Number Of Drivers: 1; Standoff Height: 0.14mm; TaMax_C: +125°C; TaMin_C: -40°C; TJmax_C: +150°C; AEC Category: Q200; CompType: IC
U8 = CMP-0073868-3: as U2 on sheet 4LP111B_DESAT.~(44)
U9 = CMP-0013230-2: Bidirectional, Low- and High-Side Measurement, Multichannel, Voltage Output, Current-Sense Amplifier, DBV0006A (SOT-6); Manufacturer: Texas Instruments; Alternate PartNumber: INA181A1IDBVT; SizeX_mm: 2.8; SizeY_mm: 2.9; CompType: IC; SizeZ_mm: 1.45; SizeArea_mm2: 8.12; SizeAreaWB_mm2: 14.82; U/M: EA

## Sheet 2LP111B_Bi-OCP_noCSA.~(38).SchDoc
size 431 x 279 mm; Date: Not shown in title block; ApprovedBy: Not shown in title block; CheckedBy: Not shown in title block; Author: Not shown in title block; CompanyName: Not shown in title block; Engineer: Not shown in title block; Organization: Not shown in title block; Address1: Not shown in title block; Address2: Not shown in title block; Address3: Not shown in title block; Address4: Not shown in title block; DocumentNumber: 1; Revision: Use project parameter SCH_Rev; SheetNumber: 1; SheetTotal: 1; PageSetup: Record=PageOptions¦CenterHorizontal=True¦CenterVertical=True¦PrintScale=1.00¦XCorrection=1.00¦YCorrection=1.00¦PrintKind=0¦BorderSize=5000000¦LeftOffset=0¦BottomOffset=0¦Orientation=2¦PaperLength=1000¦PaperWidth=1000¦Scale=100¦PaperSource=15¦PrintQuality=600¦MediaType=1¦DitherType=10¦PaperKind=Letter¦PrintScaleMode=1
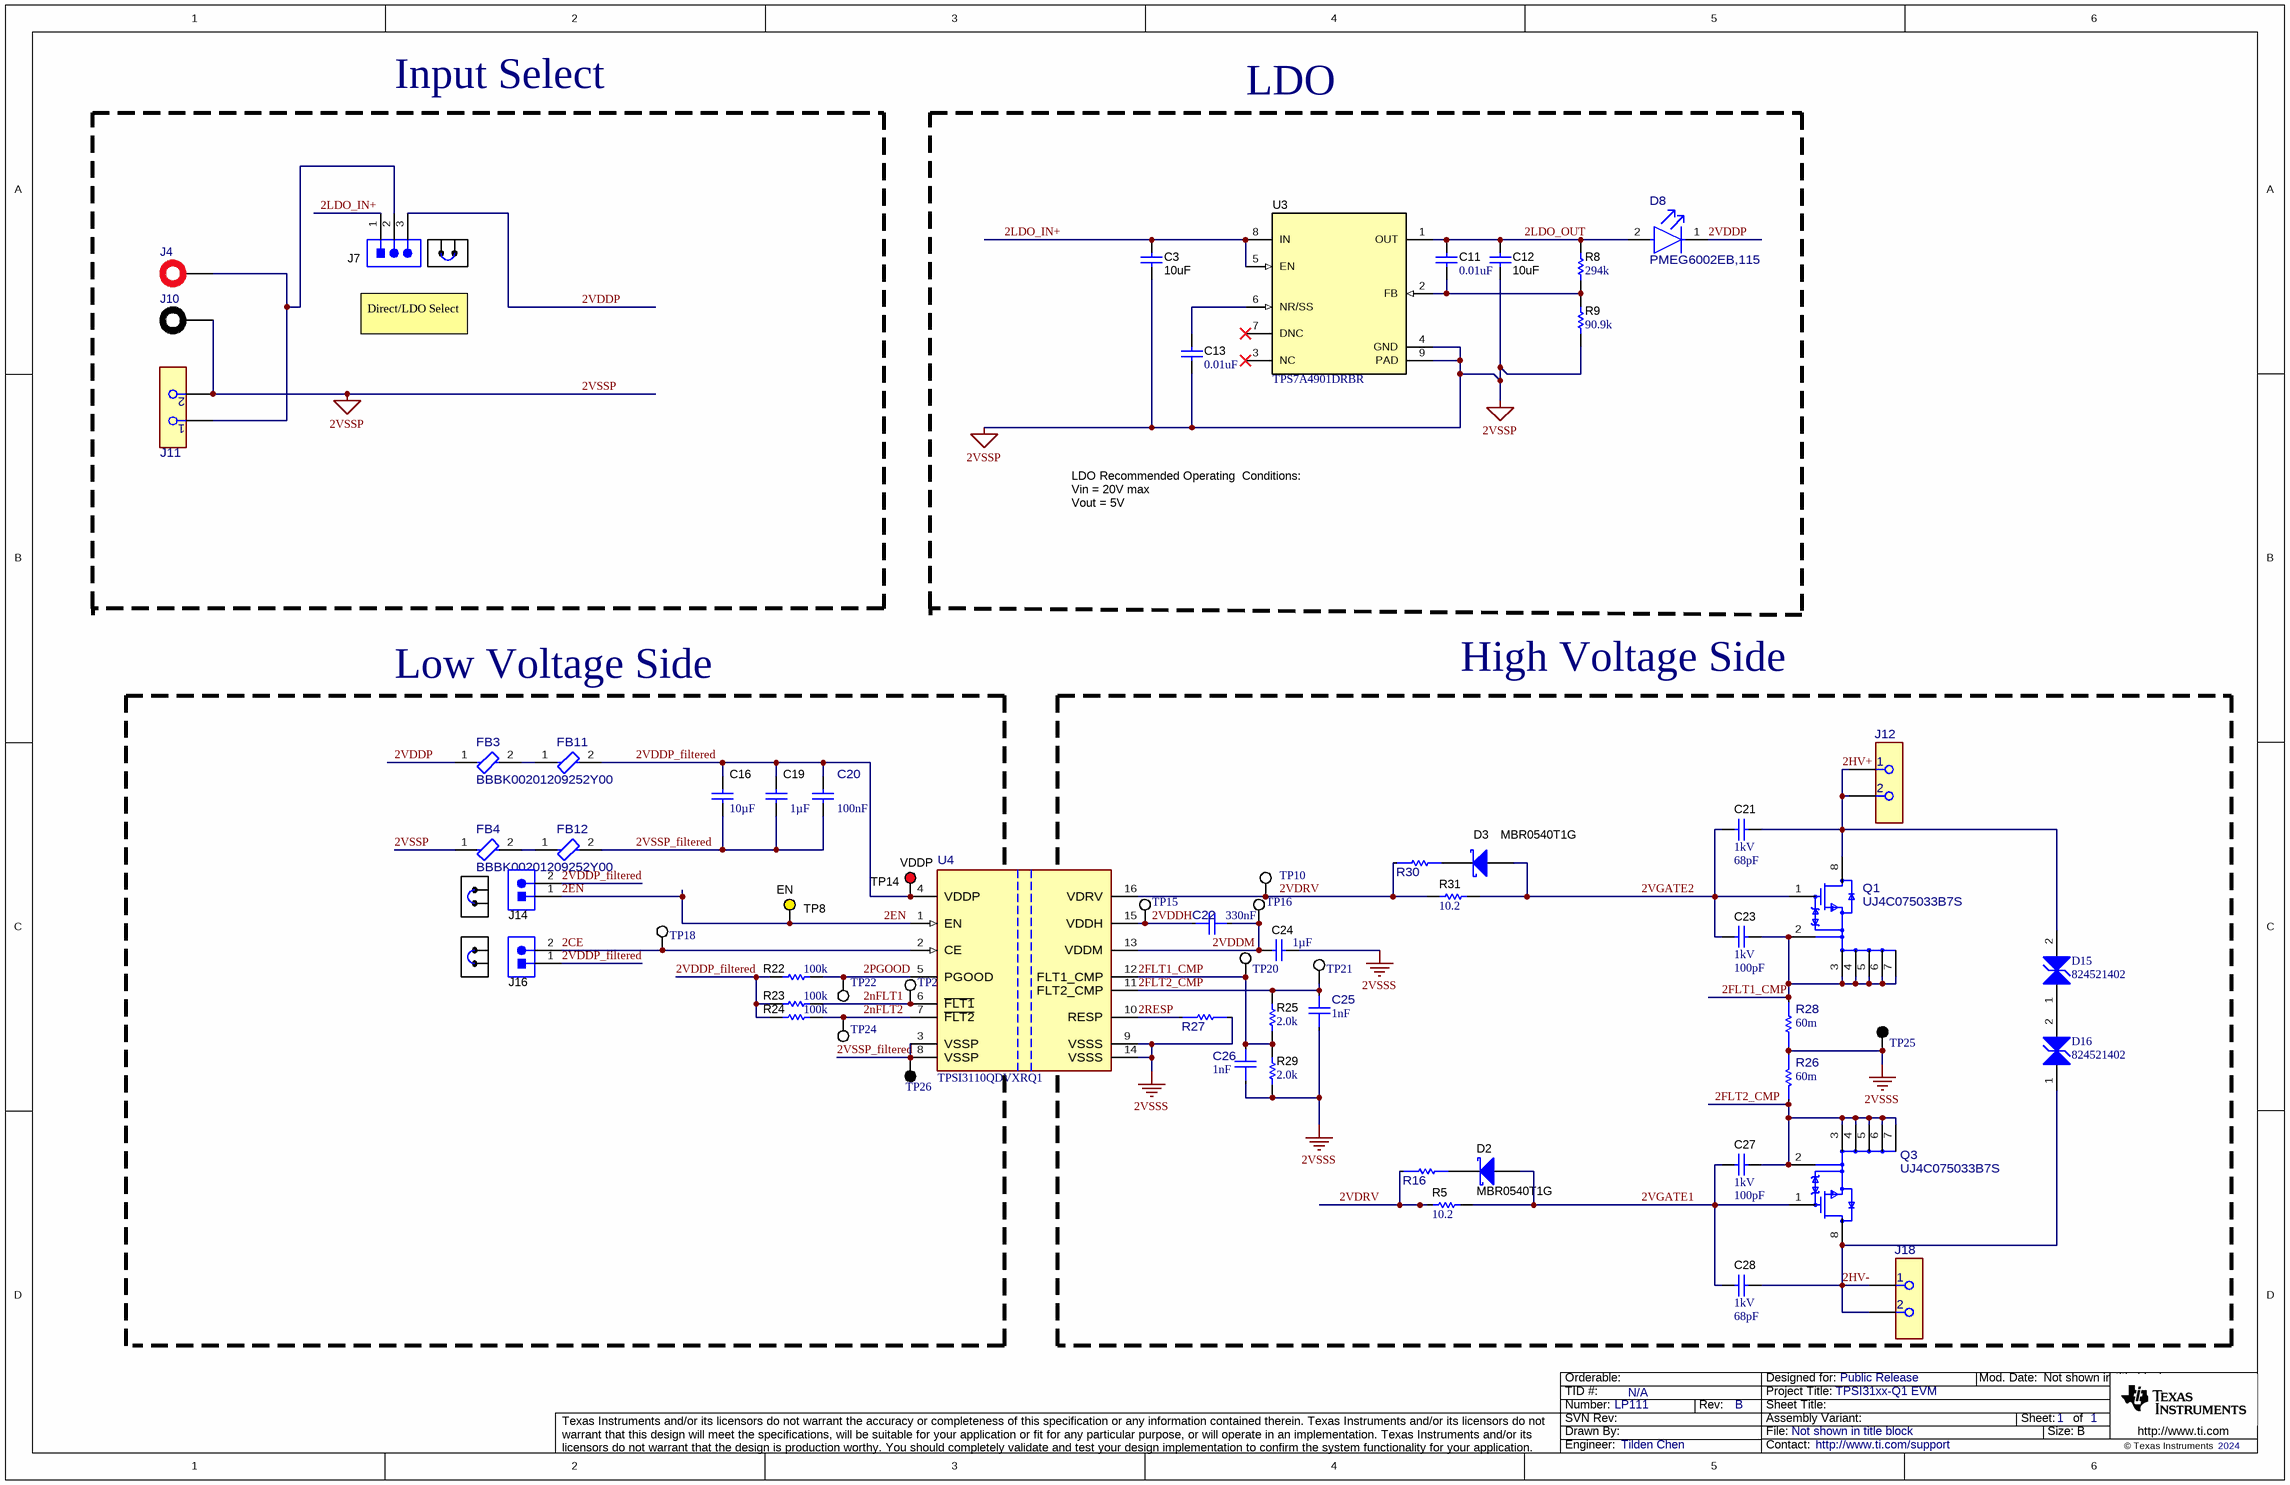
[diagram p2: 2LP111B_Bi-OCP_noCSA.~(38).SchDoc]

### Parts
C3  ValueDisplayed: 10uF  [0603]  (hidden comment: GRT188R61E106ME13D)
C11  ValueDisplayed: 0.01uF  [0402]  (hidden comment: GRM155R71E103KA01D)
C12  ValueDisplayed: 10uF  [0603]  (hidden comment: GRT188R61E106ME13D)
C13  ValueDisplayed: 0.01uF  [0402]  (hidden comment: GRM155R71E103KA01D)
C16  ValueDisplayed: 10µF  [1206_180]  (hidden comment: C1206C106J3RACAUTO)
C19  Cap_F: 1µF  [0603]  (hidden comment: GCM188R71E105KA64D)
C20  Cap_F: 100nF  [FP-C0603R104K5RAC_0603-IPC_B]  (hidden comment: C0603R104K5RAC)
C21  VDC_V: 1kV  ValueDisplayed: 68pF  [1206]  (hidden comment: GRM31A7U3A680JW31D)
C22  Cap_F: 330nF  [FP-CGA3E3X7R1E334K080AB_0603-MFG]  (hidden comment: CGA3E3X7R1E334K080AB)
C23  VDC_V: 1kV  ValueDisplayed: 100pF  [1206]  (hidden comment: GRM31A7U3A101JW31D)
C24  Cap_F: 1µF  [0603]  (hidden comment: GCM188R71E105KA64D)
C25  Cap_F: 1nF  [FP-CC0603KRX7R7BB102_0603-MFG]  (hidden comment: CC0603KRX7R7BB102)
C26  Cap_F: 1nF  [FP-CC0603KRX7R7BB102_0603-MFG]  (hidden comment: CC0603KRX7R7BB102)
C27  VDC_V: 1kV  ValueDisplayed: 100pF  [1206]  (hidden comment: GRM31A7U3A101JW31D)
C28  VDC_V: 1kV  ValueDisplayed: 68pF  [1206]  (hidden comment: GRM31A7U3A680JW31D)
D2  MBR0540T1G  [SOD-123]
D3  MBR0540T1G  [SOD-123]
D8  PMEG6002EB,115  [FP-PMEG6002EB,115_SOD523-MFG]
D15  824521402  [WE-TVSP_DO-214AA_Bidirectional]
D16  824521402  [WE-TVSP_DO-214AA_Bidirectional]
FB3  BBBK00201209252Y00  [FP-BBBK00201209252Y00_0805-MFG]
FB4  BBBK00201209252Y00  [FP-BBBK00201209252Y00_0805-MFG]
FB11  BBBK00201209252Y00  [FP-BBBK00201209252Y00_0805-MFG]  (value not drawn)
FB12  BBBK00201209252Y00  [FP-BBBK00201209252Y00_0805-MFG]  (value not drawn)
J4  108-0902-001  [Cinch_108-0902-001]  (value not drawn)
J7  PEC03SAAN  [CONN_PEC03SAAN]  (value not drawn)
J10  108-0903-001  [Cinch_108-0903-001]  (value not drawn)
J11  691250610002  [FP-691250610002_CONN_TERM_BLOCK2-MFG]  (value not drawn)
J12  691250610002  [FP-691250610002_CONN_TERM_BLOCK2-MFG]  (value not drawn)
J14  61300211121  [WURTH_61300211121]  (value not drawn)
J16  61300211121  [WURTH_61300211121]  (value not drawn)
J18  691250610002  [FP-691250610002_CONN_TERM_BLOCK2-MFG]  (value not drawn)
Q1  UJ4C075033B7S  [FP-UJ4C075033B7S_D2PAK7-MFG]
Q3  UJ4C075033B7S  [FP-UJ4C075033B7S_D2PAK7-MFG]
R5  ValueDisplayed: 10.2  [0805_HV]  (hidden comment: CRCW080510R2FKEA)
R8  ValueDisplayed: 294k  [0402]  (hidden comment: ERJ-2RKF2943X)
R9  ValueDisplayed: 90.9k  [0402]  (hidden comment: ERJ-2RKF9092X)
R16  WSL060300000ZEA9  [FP-WSL060300000ZEA9_0603-MFG]  (value not drawn)
R22  ValueDisplayed: 100k  [0805_HV]  (hidden comment: ERJ-6GEYJ104V)
R23  ValueDisplayed: 100k  [0805_HV]  (hidden comment: ERJ-6GEYJ104V)
R24  ValueDisplayed: 100k  [0805_HV]  (hidden comment: ERJ-6GEYJ104V)
R25  ValueDisplayed: 2.0k  [0603]  (hidden comment: RC0603JR-072KL)
R26  value 60m  [FP-CRA2512-FZ-R060ELF_2512-MFG]  (hidden comment: CRA2512-FZ-R060ELF)
R27  WSL060300000ZEA9  [FP-WSL060300000ZEA9_0603-MFG]  (value not drawn)
R28  value 60m  [FP-CRA2512-FZ-R060ELF_2512-MFG]  (hidden comment: CRA2512-FZ-R060ELF)
R29  ValueDisplayed: 2.0k  [0603]  (hidden comment: RC0603JR-072KL)
R30  WSL060300000ZEA9  [FP-WSL060300000ZEA9_0603-MFG]  (value not drawn)
R31  ValueDisplayed: 10.2  [0805_HV]  (hidden comment: CRCW080510R2FKEA)
SH-J4  SNT-100-BK-G  [SNT-100-BK-G]  (value not drawn)
SH-J5  SNT-100-BK-G  [SNT-100-BK-G]  (value not drawn)
SH-J6  SNT-100-BK-G  [SNT-100-BK-G]  (value not drawn)
TP8  EN  [Keystone5014]
TP10  5012  [KSTN-5012_V]  (value not drawn)
TP14  VDDP  [Keystone5010]
TP15  5012  [KSTN-5012_V]  (value not drawn)
TP16  5012  [KSTN-5012_V]  (value not drawn)
TP18  5012  [KSTN-5012_V]  (value not drawn)
TP20  5012  [KSTN-5012_V]  (value not drawn)
TP21  5012  [KSTN-5012_V]  (value not drawn)
TP22  5012  [KSTN-5012_V]  (value not drawn)
TP23  5012  [KSTN-5012_V]  (value not drawn)
TP24  5012  [KSTN-5012_V]  (value not drawn)
TP25  5011  [Keystone5011]  (value not drawn)
TP26  5011  [Keystone5011]  (value not drawn)
U3  TPS7A4901DRBR  [DRB0008A]
U4  TPSI3110QDVXRQ1  [DVX0016A-MFG]

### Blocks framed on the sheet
High Voltage Side: C21-C28 D2 D3 D15 D16 J12 J18 Q1 Q3 R5 R16 R25-R31 TP10 TP15 TP16 TP20 TP21 TP25

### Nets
2VSSP: C3.2 C12.2 C13.2 FB4.1 J10.1 J11.2 R9.1 U3.4(GND) U3.9(PAD)
2VSSS: C24.1 C25.1 C26.1 R26.1 R27.2 R28.1 R29.1 TP25.1 U4.9(VSSS) U4.14(VSSS)
2CE: J16.2 TP18.1 U4.2(CE)
2EN: J14.1 TP8.1 U4.1(EN)
2FLT1_CMP: C23.1 C26.2 Q1.2(KS) Q1.3(S) Q1.4(S) Q1.5(S) Q1.6(S) Q1.7(S) R25.1 R28.2 R29.2 TP20.1 U4.12(FLT1_CMP)
2FLT2_CMP: C25.2 C27.1 Q3.2(KS) Q3.3(S) Q3.4(S) Q3.5(S) Q3.6(S) Q3.7(S) R25.2 R26.2 TP21.1 U4.11(FLT2_CMP)
2HV+: C21.1 D15.2 J12.1 J12.2 Q1.8(D)
2HV-: C28.1 D16.1 J18.1 J18.2 Q3.8(D)
2LDO_IN+: C3.1 J7.1 U3.5(EN) U3.8(IN)
2LDO_OUT: C11.1 C12.1 D8.2(ANODE) R8.2 U3.1(OUT)
2nFLT1: R23.2 TP23.1 U4.6(~{FLT1})
2nFLT2: R24.2 TP24.1 U4.7(~{FLT2})
2PGOOD: R22.2 TP22.1 U4.5(PGOOD)
2RESP: R27.1 U4.10(RESP)
2VDDH: C22.1 TP15.1 U4.15(VDDH)
2VDDM: C22.2 C24.2 TP16.1 U4.13(VDDM)
2VDDP: D8.1(CATHODE) FB3.1 J7.3
2VDDP_filtered: C16.1 C19.1 C20.2 FB11.2 J14.2 J16.1 R22.1 R23.1 R24.1 TP14.1 U4.4(VDDP)
2VDRV: R5.1 R16.1 R30.1 R31.1 TP10.1 U4.16(VDRV)
2VGATE1: C27.2 C28.2 D2.2(A) Q3.1(G) R5.2
2VGATE2: C21.2 C23.2 D3.2(A) Q1.1(G) R31.2
2VSSP_filtered: C16.2 C19.2 C20.1 FB12.2 TP26.1 U4.3(VSSP) U4.8(VSSP)
NetC11_2: C11.2 R8.1 R9.2 U3.2(FB)
NetC13_1: C13.1 U3.6(NR/SS)
NetD2_1: D2.1(K) R16.2
NetD3_1: D3.1(K) R30.2
NetD15_1: D15.1 D16.2
NetFB3_2: FB3.2 FB11.1
NetFB4_2: FB4.2 FB12.1
NetJ4_1: J4.1 J7.2 J11.1

Not connected (* = marked no-connect by the designer): U3 3(NC)* 7(DNC)*

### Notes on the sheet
- Input Select
- LDO
- Direct/LDO Select
- LDO Recommended Operating  Conditions:
  Vin = 20V max
  Vout = 5V
- Low Voltage Side

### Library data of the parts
C3 C12 = CMP-0007501-1: as C5 on sheet 4LP111B_DESAT.~(44)
C11 C13 = CMP-0006658-2: as C7 on sheet 4LP111B_DESAT.~(44)
C16 = CMP-0081062-1: as C1 on sheet 4LP111B_DESAT.~(44)
C19 C24 = CMP-0007139-4: as C2 on sheet 4LP111B_DESAT.~(44)
C20 = CMP-0087061-2: as C4 on sheet 4LP111B_DESAT.~(44)
C21 C28 = CMP-0008902-2: as C54 on sheet 3LP111B_Uni-OCP_CSA.~(35)
C22 = CMP-0030960-1: as C6 on sheet 4LP111B_DESAT.~(44)
C23 C27 = CMP-0008897-2: as C18 on sheet 4LP111B_DESAT.~(44)
C25 C26 = CMP-0094870-1: as C8 on sheet 4LP111B_DESAT.~(44)
D2 D3 = CMP-0028526-2: as D1 on sheet 4LP111B_DESAT.~(44)
D8 = CMP-0087203-1: as D5 on sheet 4LP111B_DESAT.~(44)
D15 D16 = CMP-03913-133963857-1: 824521402 Tvs Diode, Bidir, 400V, Do-214Aa Rohs Compliant: Yes; Leakage Current: 1µA
FB3 FB4 FB11 FB12 = CMP-0124406-1: as FB1 on sheet 4LP111B_DESAT.~(44)
J4 = CMP-0079575-1: as J1 on sheet 4LP111B_DESAT.~(44)
J7 = CMP-0002338-1: as J5 on sheet 4LP111B_DESAT.~(44)
J10 = CMP-0079574-1: as J2 on sheet 4LP111B_DESAT.~(44)
J11 J12 J18 = CMP-0093233-2: as J3 on sheet 4LP111B_DESAT.~(44)
J14 J16 = CMP-0054794-2: as J6 on sheet 4LP111B_DESAT.~(44)
Q1 Q3 = CMP-0120465-1: as Q5 on sheet 3LP111B_Uni-OCP_CSA.~(35)
R5 R31 = CMP-0020848-3: as R10 on sheet 4LP111B_DESAT.~(44)
R8 = CMP-0026693-1: as R11 on sheet 4LP111B_DESAT.~(44)
R9 = CMP-0026711-1: as R12 on sheet 4LP111B_DESAT.~(44)
R16 R27 R30 = CMP-0031931-1: as R4 on sheet 4LP111B_DESAT.~(44)
R22-R24 = CMP-0020622-3: as R1 on sheet 4LP111B_DESAT.~(44)
R25 R29 = CMP-0025909-5: as R42 on sheet 3LP111B_Uni-OCP_CSA.~(35)
R26 R28 = CMP-0123876-1: Res Metal Strip 2512 0.06 Ohm 1% 3W ±50ppm/°C Pad SMD Automotive T/R; Manufacturer: Bourns; AEC Grade: Grade 0; AEC Qualified: Yes; SizeZ_mm: 0.9mm
SH-J4-SH-J6 = CMP-0003623-3: as SH-J1 on sheet 4LP111B_DESAT.~(44)
TP8 = CMP-0055151-2: as TP2 on sheet 4LP111B_DESAT.~(44)
TP10 TP15 TP16 TP18 TP20-TP24 = CMP-1672-00004-4: as TP1 on sheet 4LP111B_DESAT.~(44)
TP14 = CMP-0055147-2: as TP5 on sheet 4LP111B_DESAT.~(44)
TP25 TP26 = CMP-0055148-2: as TP6 on sheet 4LP111B_DESAT.~(44)
U3 = CMP-0073868-3: as U2 on sheet 4LP111B_DESAT.~(44)
U4 = CMP-0001684-2: Automotive Reinforced Isolated Switch Driver with Integrated 15-V Gate Supply and Fault Indicators; Manufacturer: Texas Instruments; SizeZ_mm: 2.6mm; AEC Qualified: Yes; AEC Grade: Grade 1; Max Power Dissipation: 250mW; Max Supply Voltage: 5.5V; Min Supply Voltage: 4.5V; Number Of Drivers: 1; Standoff Height: 0.14mm; TaMax_C: +125°C; TaMin_C: -40°C; TJmax_C: +150°C; AEC Category: Q200; CompType: IC

## Sheet 1LP111B_Uni-OCP_noCSA.~(35).SchDoc
size 431 x 279 mm; Date: Not shown in title block; ApprovedBy: Not shown in title block; CheckedBy: Not shown in title block; Author: Not shown in title block; CompanyName: Not shown in title block; Engineer: Not shown in title block; Organization: Not shown in title block; Address1: Not shown in title block; Address2: Not shown in title block; Address3: Not shown in title block; Address4: Not shown in title block; DocumentNumber: 1; Revision: Use project parameter SCH_Rev; SheetNumber: 1; SheetTotal: 1; PageSetup: Record=PageOptions¦CenterHorizontal=True¦CenterVertical=True¦PrintScale=1.00¦XCorrection=1.00¦YCorrection=1.00¦PrintKind=0¦BorderSize=5000000¦LeftOffset=0¦BottomOffset=0¦Orientation=2¦PaperLength=1000¦PaperWidth=1000¦Scale=100¦PaperSource=15¦PrintQuality=600¦MediaType=1¦DitherType=10¦PaperKind=Letter¦PrintScaleMode=1
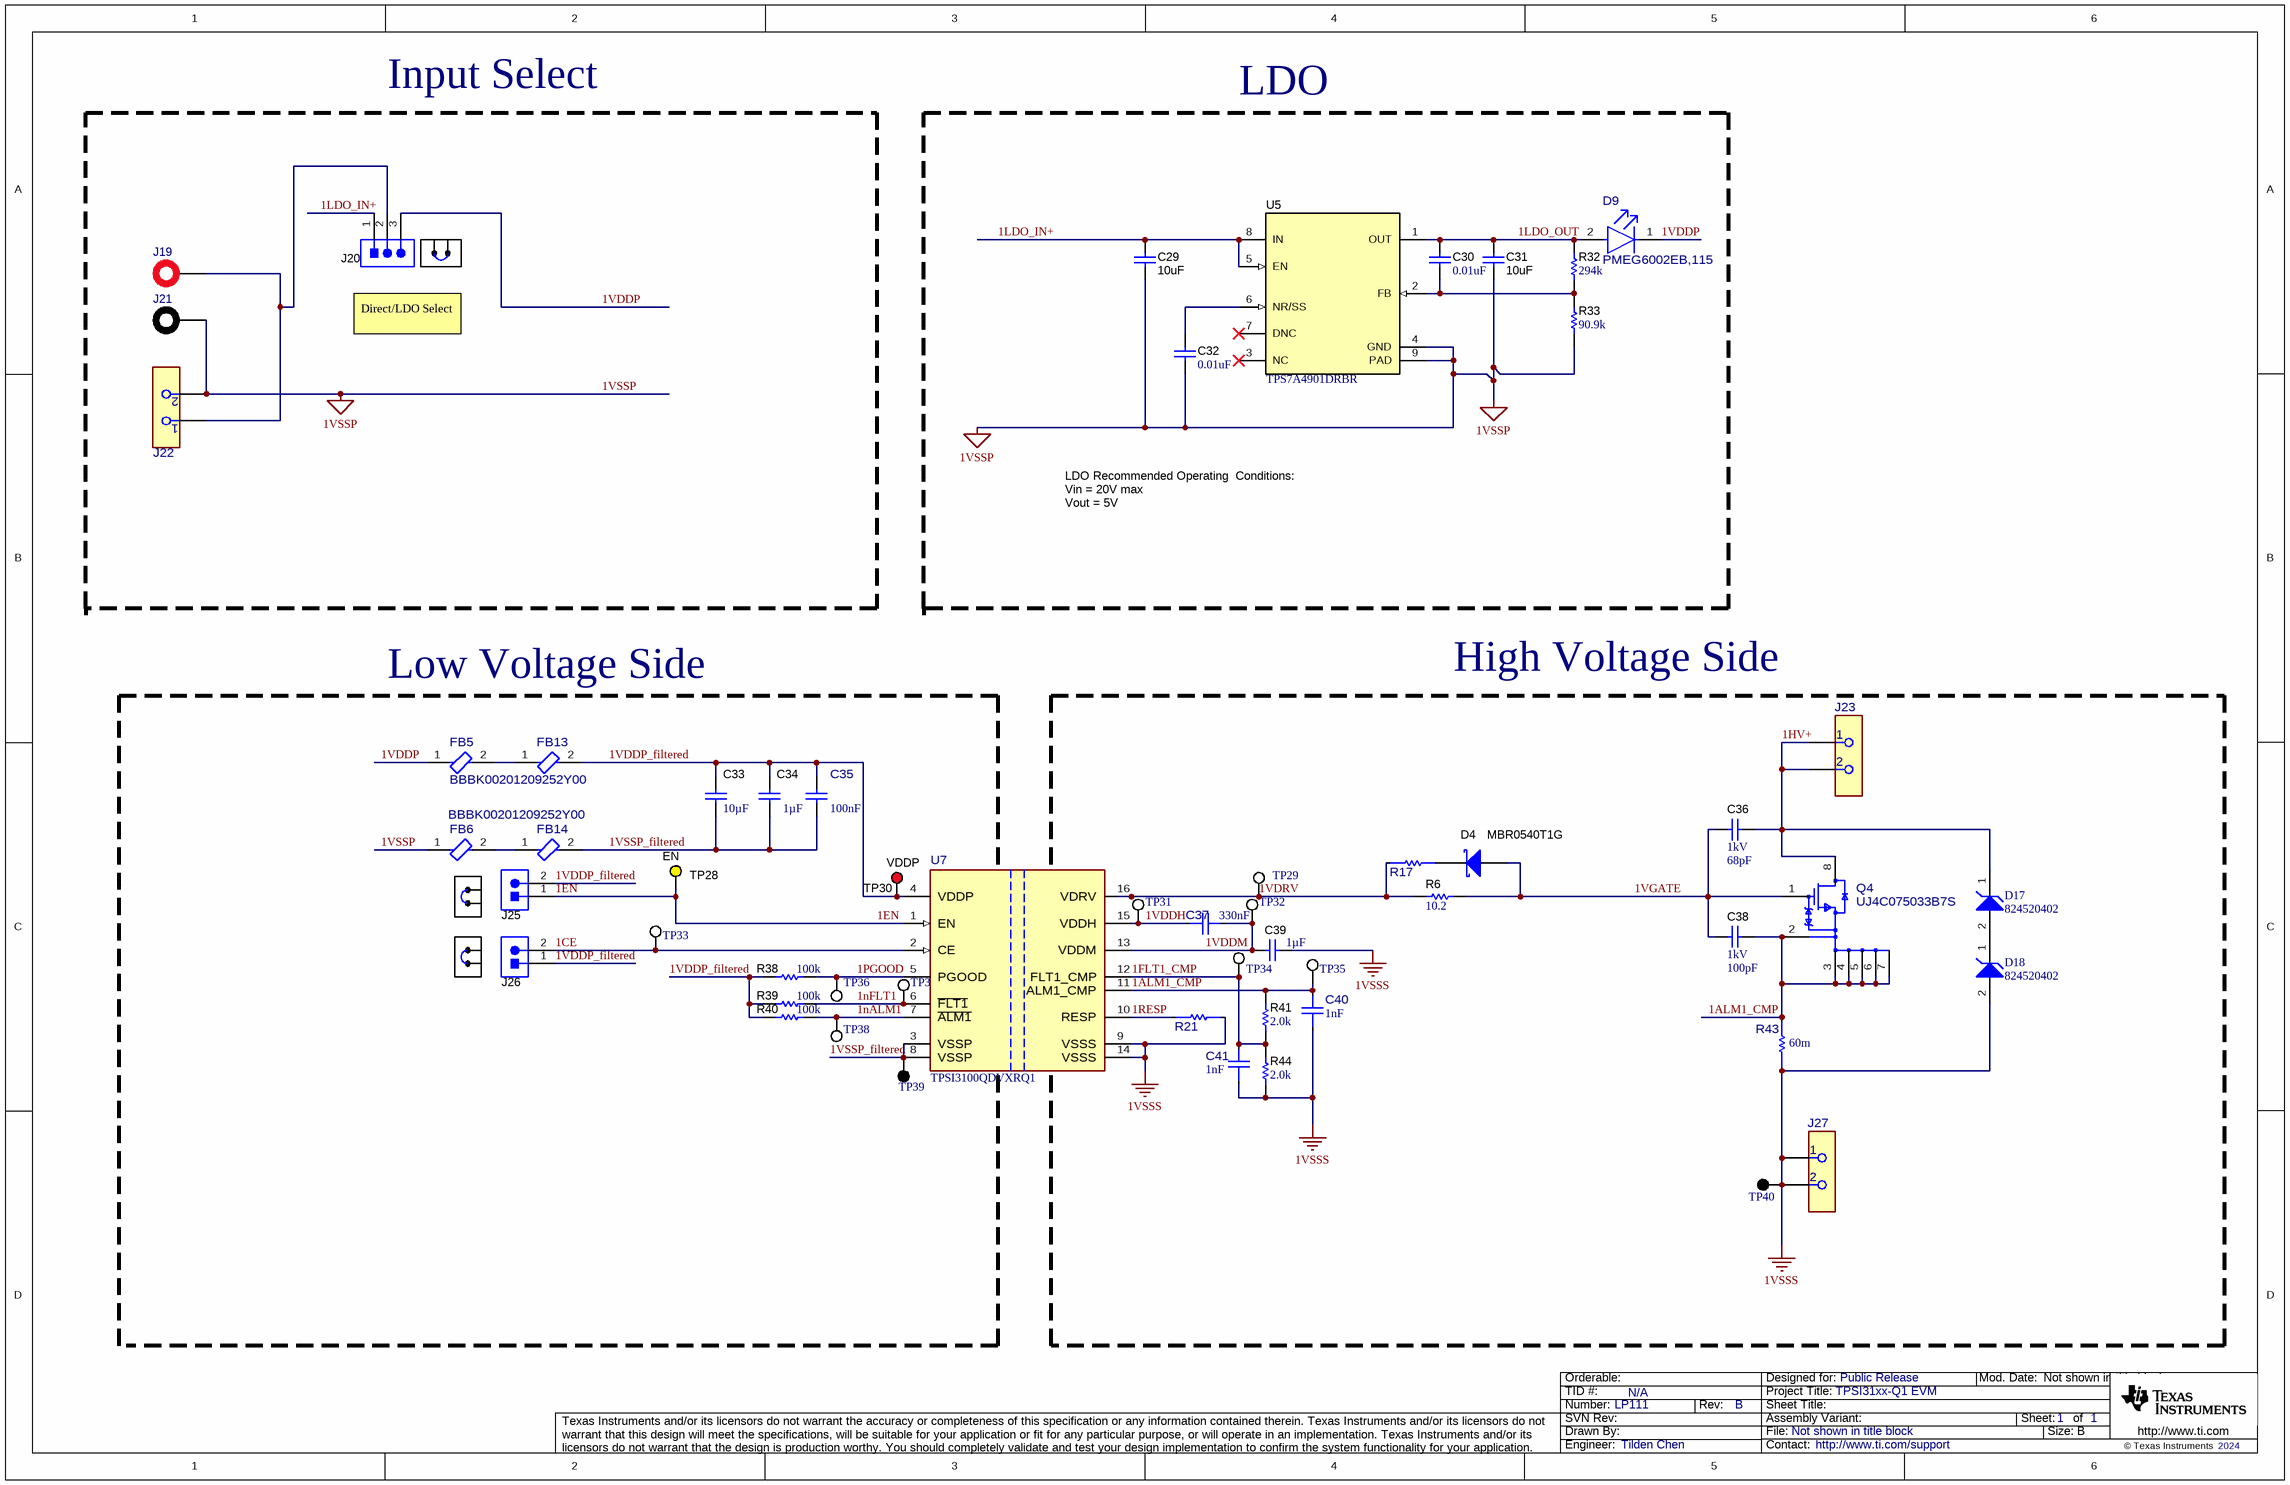
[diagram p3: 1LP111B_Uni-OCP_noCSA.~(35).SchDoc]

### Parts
C29  ValueDisplayed: 10uF  [0603]  (hidden comment: GRT188R61E106ME13D)
C30  ValueDisplayed: 0.01uF  [0402]  (hidden comment: GRM155R71E103KA01D)
C31  ValueDisplayed: 10uF  [0603]  (hidden comment: GRT188R61E106ME13D)
C32  ValueDisplayed: 0.01uF  [0402]  (hidden comment: GRM155R71E103KA01D)
C33  ValueDisplayed: 10µF  [1206_180]  (hidden comment: C1206C106J3RACAUTO)
C34  Cap_F: 1µF  [0603]  (hidden comment: GCM188R71E105KA64D)
C35  Cap_F: 100nF  [FP-C0603R104K5RAC_0603-IPC_B]  (hidden comment: C0603R104K5RAC)
C36  VDC_V: 1kV  ValueDisplayed: 68pF  [1206]  (hidden comment: GRM31A7U3A680JW31D)
C37  Cap_F: 330nF  [FP-CGA3E3X7R1E334K080AB_0603-MFG]  (hidden comment: CGA3E3X7R1E334K080AB)
C38  VDC_V: 1kV  ValueDisplayed: 100pF  [1206]  (hidden comment: GRM31A7U3A101JW31D)
C39  Cap_F: 1µF  [0603]  (hidden comment: GCM188R71E105KA64D)
C40  Cap_F: 1nF  [FP-CC0603KRX7R7BB102_0603-MFG]  (hidden comment: CC0603KRX7R7BB102)
C41  Cap_F: 1nF  [FP-CC0603KRX7R7BB102_0603-MFG]  (hidden comment: CC0603KRX7R7BB102)
D4  MBR0540T1G  [SOD-123]
D9  PMEG6002EB,115  [FP-PMEG6002EB,115_SOD523-MFG]
D17  824520402  [WE-TVSP_DO-214AA_Unidirectional]
D18  824520402  [WE-TVSP_DO-214AA_Unidirectional]
FB5  BBBK00201209252Y00  [FP-BBBK00201209252Y00_0805-MFG]
FB6  BBBK00201209252Y00  [FP-BBBK00201209252Y00_0805-MFG]
FB13  BBBK00201209252Y00  [FP-BBBK00201209252Y00_0805-MFG]  (value not drawn)
FB14  BBBK00201209252Y00  [FP-BBBK00201209252Y00_0805-MFG]  (value not drawn)
J19  108-0902-001  [Cinch_108-0902-001]  (value not drawn)
J20  PEC03SAAN  [CONN_PEC03SAAN]  (value not drawn)
J21  108-0903-001  [Cinch_108-0903-001]  (value not drawn)
J22  691250610002  [FP-691250610002_CONN_TERM_BLOCK2-MFG]  (value not drawn)
J23  691250610002  [FP-691250610002_CONN_TERM_BLOCK2-MFG]  (value not drawn)
J25  61300211121  [WURTH_61300211121]  (value not drawn)
J26  61300211121  [WURTH_61300211121]  (value not drawn)
J27  691250610002  [FP-691250610002_CONN_TERM_BLOCK2-MFG]  (value not drawn)
Q4  UJ4C075033B7S  [FP-UJ4C075033B7S_D2PAK7-MFG]
R6  ValueDisplayed: 10.2  [0805_HV]  (hidden comment: CRCW080510R2FKEA)
R17  WSL060300000ZEA9  [FP-WSL060300000ZEA9_0603-MFG]  (value not drawn)
R21  WSL060300000ZEA9  [FP-WSL060300000ZEA9_0603-MFG]  (value not drawn)
R32  ValueDisplayed: 294k  [0402]  (hidden comment: ERJ-2RKF2943X)
R33  ValueDisplayed: 90.9k  [0402]  (hidden comment: ERJ-2RKF9092X)
R38  ValueDisplayed: 100k  [0805_HV]  (hidden comment: ERJ-6GEYJ104V)
R39  ValueDisplayed: 100k  [0805_HV]  (hidden comment: ERJ-6GEYJ104V)
R40  ValueDisplayed: 100k  [0805_HV]  (hidden comment: ERJ-6GEYJ104V)
R41  ValueDisplayed: 2.0k  [0603]  (hidden comment: RC0603JR-072KL)
R43  value 60m  [FP-CRA2512-FZ-R060ELF_2512-MFG]  (hidden comment: CRA2512-FZ-R060ELF)
R44  ValueDisplayed: 2.0k  [0603]  (hidden comment: RC0603JR-072KL)
SH-J7  SNT-100-BK-G  [SNT-100-BK-G]  (value not drawn)
SH-J8  SNT-100-BK-G  [SNT-100-BK-G]  (value not drawn)
SH-J9  SNT-100-BK-G  [SNT-100-BK-G]  (value not drawn)
TP28  EN  [Keystone5014]
TP29  5012  [KSTN-5012_V]  (value not drawn)
TP30  VDDP  [Keystone5010]
TP31  5012  [KSTN-5012_V]  (value not drawn)
TP32  5012  [KSTN-5012_V]  (value not drawn)
TP33  5012  [KSTN-5012_V]  (value not drawn)
TP34  5012  [KSTN-5012_V]  (value not drawn)
TP35  5012  [KSTN-5012_V]  (value not drawn)
TP36  5012  [KSTN-5012_V]  (value not drawn)
TP37  5012  [KSTN-5012_V]  (value not drawn)
TP38  5012  [KSTN-5012_V]  (value not drawn)
TP39  5011  [Keystone5011]  (value not drawn)
TP40  5011  [Keystone5011]  (value not drawn)
U5  TPS7A4901DRBR  [DRB0008A]
U7  TPSI3100QDVXRQ1  [DVX0016A-MFG]

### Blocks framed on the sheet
High Voltage Side: C36-C41 D4 D17 D18 J23 J27 Q4 R6 R17 R21 R41 R43 R44 TP29 TP31 TP32 TP34 TP35 TP40

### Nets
1VSSP: C29.2 C31.2 C32.2 FB6.1 J21.1 J22.2 R33.1 U5.4(GND) U5.9(PAD)
1VSSS: C39.1 C40.1 C41.1 D18.2(A) J27.1 J27.2 R21.2 R43.1 R44.1 TP40.1 U7.9(VSSS) U7.14(VSSS)
1ALM1_CMP: C38.1 C40.2 Q4.2(KS) Q4.3(S) Q4.4(S) Q4.5(S) Q4.6(S) Q4.7(S) R41.2 R43.2 TP35.1 U7.11(ALM1_CMP)
1CE: J26.2 TP33.1 U7.2(CE)
1EN: J25.1 TP28.1 U7.1(EN)
1FLT1_CMP: C41.2 R41.1 R44.2 TP34.1 U7.12(FLT1_CMP)
1HV+: C36.1 D17.1(K) J23.1 J23.2 Q4.8(D)
1LDO_IN+: C29.1 J20.1 U5.5(EN) U5.8(IN)
1LDO_OUT: C30.1 C31.1 D9.2(ANODE) R32.2 U5.1(OUT)
1nALM1: R40.2 TP38.1 U7.7(~{ALM1})
1nFLT1: R39.2 TP37.1 U7.6(~{FLT1})
1PGOOD: R38.2 TP36.1 U7.5(PGOOD)
1RESP: R21.1 U7.10(RESP)
1VDDH: C37.1 TP31.1 U7.15(VDDH)
1VDDM: C37.2 C39.2 TP32.1 U7.13(VDDM)
1VDDP: D9.1(CATHODE) FB5.1 J20.3
1VDDP_filtered: C33.1 C34.1 C35.2 FB13.2 J25.2 J26.1 R38.1 R39.1 R40.1 TP30.1 U7.4(VDDP)
1VDRV: R6.1 R17.1 TP29.1 U7.16(VDRV)
1VGATE: C36.2 C38.2 D4.2(A) Q4.1(G) R6.2
1VSSP_filtered: C33.2 C34.2 C35.1 FB14.2 TP39.1 U7.3(VSSP) U7.8(VSSP)
NetC30_2: C30.2 R32.1 R33.2 U5.2(FB)
NetC32_1: C32.1 U5.6(NR/SS)
NetD4_1: D4.1(K) R17.2
NetD17_2: D17.2(A) D18.1(K)
NetFB5_2: FB5.2 FB13.1
NetFB6_2: FB6.2 FB14.1
NetJ19_1: J19.1 J20.2 J22.1

Not connected (* = marked no-connect by the designer): U5 3(NC)* 7(DNC)*

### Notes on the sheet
- Input Select
- LDO
- Direct/LDO Select
- LDO Recommended Operating  Conditions:
  Vin = 20V max
  Vout = 5V
- Low Voltage Side

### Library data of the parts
C29 C31 = CMP-0007501-1: as C5 on sheet 4LP111B_DESAT.~(44)
C30 C32 = CMP-0006658-2: as C7 on sheet 4LP111B_DESAT.~(44)
C33 = CMP-0081062-1: as C1 on sheet 4LP111B_DESAT.~(44)
C34 C39 = CMP-0007139-4: as C2 on sheet 4LP111B_DESAT.~(44)
C35 = CMP-0087061-2: as C4 on sheet 4LP111B_DESAT.~(44)
C36 = CMP-0008902-2: as C54 on sheet 3LP111B_Uni-OCP_CSA.~(35)
C37 = CMP-0030960-1: as C6 on sheet 4LP111B_DESAT.~(44)
C38 = CMP-0008897-2: as C18 on sheet 4LP111B_DESAT.~(44)
C40 C41 = CMP-0094870-1: as C8 on sheet 4LP111B_DESAT.~(44)
D4 = CMP-0028526-2: as D1 on sheet 4LP111B_DESAT.~(44)
D9 = CMP-0087203-1: as D5 on sheet 4LP111B_DESAT.~(44)
D17 D18 = CMP-03913-133963852-1: as D7 on sheet 4LP111B_DESAT.~(44)
FB5 FB6 FB13 FB14 = CMP-0124406-1: as FB1 on sheet 4LP111B_DESAT.~(44)
J19 = CMP-0079575-1: as J1 on sheet 4LP111B_DESAT.~(44)
J20 = CMP-0002338-1: as J5 on sheet 4LP111B_DESAT.~(44)
J21 = CMP-0079574-1: as J2 on sheet 4LP111B_DESAT.~(44)
J22 J23 J27 = CMP-0093233-2: as J3 on sheet 4LP111B_DESAT.~(44)
J25 J26 = CMP-0054794-2: as J6 on sheet 4LP111B_DESAT.~(44)
Q4 = CMP-0120465-1: as Q5 on sheet 3LP111B_Uni-OCP_CSA.~(35)
R6 = CMP-0020848-3: as R10 on sheet 4LP111B_DESAT.~(44)
R17 R21 = CMP-0031931-1: as R4 on sheet 4LP111B_DESAT.~(44)
R32 = CMP-0026693-1: as R11 on sheet 4LP111B_DESAT.~(44)
R33 = CMP-0026711-1: as R12 on sheet 4LP111B_DESAT.~(44)
R38-R40 = CMP-0020622-3: as R1 on sheet 4LP111B_DESAT.~(44)
R41 R44 = CMP-0025909-5: as R42 on sheet 3LP111B_Uni-OCP_CSA.~(35)
R43 = CMP-0123876-1: as R26 on sheet 2LP111B_Bi-OCP_noCSA.~(38)
SH-J7-SH-J9 = CMP-0003623-3: as SH-J1 on sheet 4LP111B_DESAT.~(44)
TP28 = CMP-0055151-2: as TP2 on sheet 4LP111B_DESAT.~(44)
TP29 TP31-TP38 = CMP-1672-00004-4: as TP1 on sheet 4LP111B_DESAT.~(44)
TP30 = CMP-0055147-2: as TP5 on sheet 4LP111B_DESAT.~(44)
TP39 TP40 = CMP-0055148-2: as TP6 on sheet 4LP111B_DESAT.~(44)
U5 = CMP-0073868-3: as U2 on sheet 4LP111B_DESAT.~(44)
U7 = CMP-0029491-2: as U6 on sheet 3LP111B_Uni-OCP_CSA.~(35)

## Sheet LP111A_Hardware.SchDoc
size 431 x 279 mm; Date: Not shown in title block; ApprovedBy: Not shown in title block; CheckedBy: Not shown in title block; Author: Not shown in title block; CompanyName: Not shown in title block; DrawnBy: Tilden Chen; Engineer: Not shown in title block; Organization: Not shown in title block; Address1: Not shown in title block; Address2: Not shown in title block; Address3: Not shown in title block; Address4: Not shown in title block; DocumentNumber: 3; Revision: Use project parameter SCH_Rev; SheetNumber: 2; SheetTotal: 2; PageSetup: Record=PageOptions¦CenterHorizontal=True¦CenterVertical=True¦PrintScale=1.00¦XCorrection=1.00¦YCorrection=1.00¦PrintKind=0¦BorderSize=5000000¦LeftOffset=0¦BottomOffset=0¦Orientation=2¦PaperLength=1000¦PaperWidth=1000¦Scale=100¦PaperSource=15¦PrintQuality=600¦MediaType=1¦DitherType=10¦PaperKind=Letter¦PrintScaleMode=1
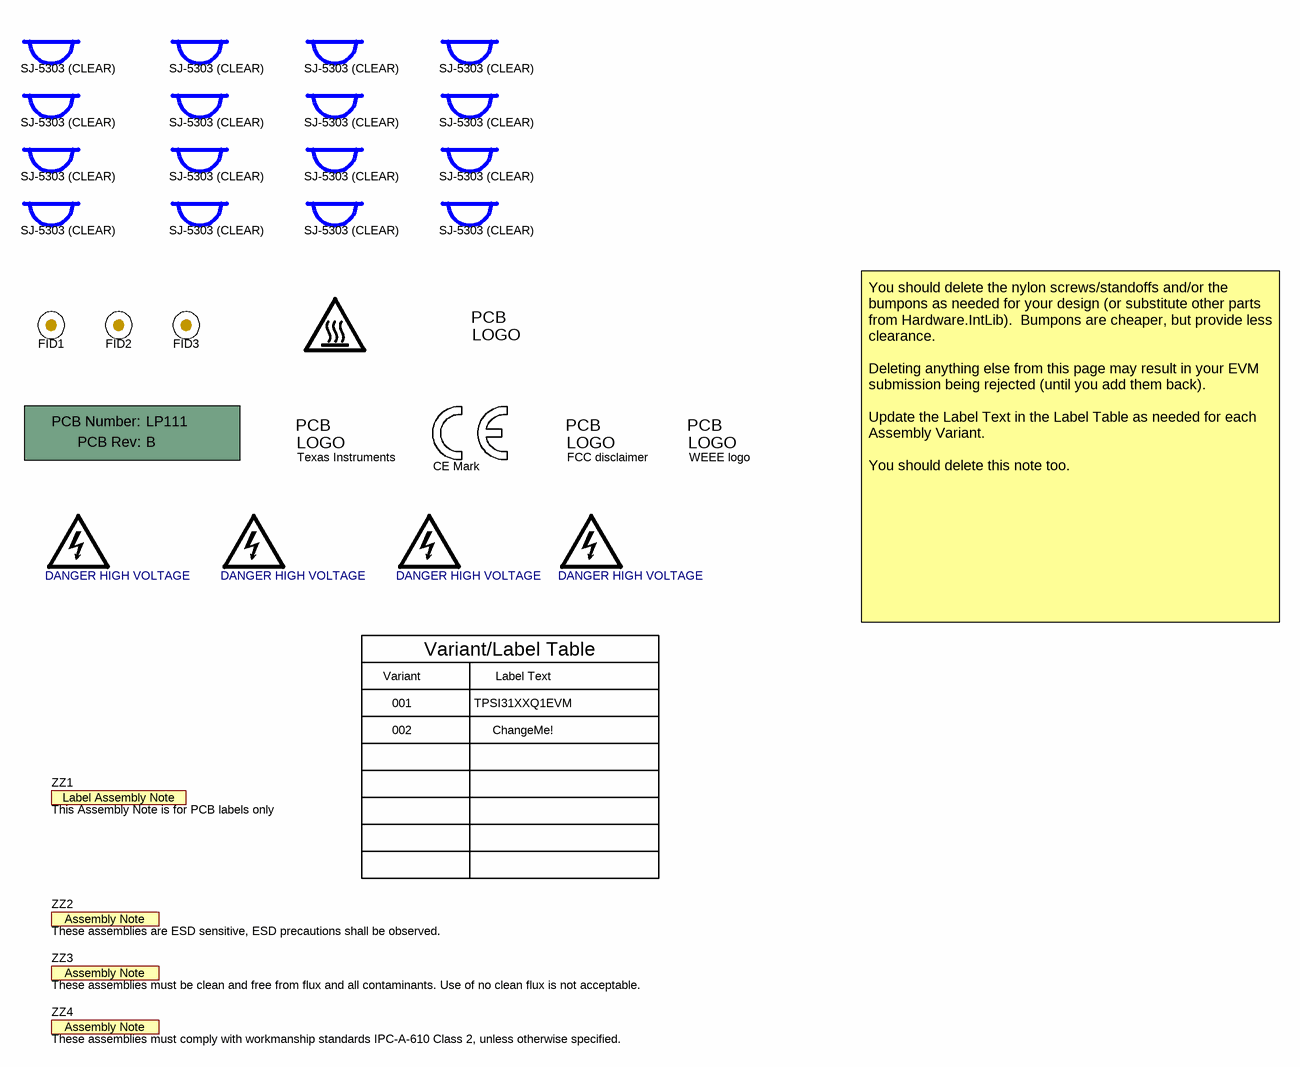
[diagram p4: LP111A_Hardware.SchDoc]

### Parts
!PCB1  Printed Circuit Board  (value not drawn)  (mechanical)
FID1  Fiducial  [Fiducial10-20]  (value not drawn)
FID2  Fiducial  [Fiducial10-20]  (value not drawn)
FID3  Fiducial  [Fiducial10-20]  (value not drawn)
H1  SJ-5303 (CLEAR)  [Bumpon_SJ5003Transparent]
H2  SJ-5303 (CLEAR)  [Bumpon_SJ5003Transparent]
H3  SJ-5303 (CLEAR)  [Bumpon_SJ5003Transparent]
H4  SJ-5303 (CLEAR)  [Bumpon_SJ5003Transparent]
H5  SJ-5303 (CLEAR)  [Bumpon_SJ5003Transparent]
H6  SJ-5303 (CLEAR)  [Bumpon_SJ5003Transparent]
H7  SJ-5303 (CLEAR)  [Bumpon_SJ5003Transparent]
H8  SJ-5303 (CLEAR)  [Bumpon_SJ5003Transparent]
H9  SJ-5303 (CLEAR)  [Bumpon_SJ5003Transparent]
H10  SJ-5303 (CLEAR)  [Bumpon_SJ5003Transparent]
H11  SJ-5303 (CLEAR)  [Bumpon_SJ5003Transparent]
H12  SJ-5303 (CLEAR)  [Bumpon_SJ5003Transparent]
H13  SJ-5303 (CLEAR)  [Bumpon_SJ5003Transparent]
H14  SJ-5303 (CLEAR)  [Bumpon_SJ5003Transparent]
H15  SJ-5303 (CLEAR)  [Bumpon_SJ5003Transparent]
H16  SJ-5303 (CLEAR)  [Bumpon_SJ5003Transparent]
Logo1  CE Mark  [CE_Mark_5mm]  (no BOM)
Logo2  Texas Instruments  [TI_Stacked_Overlay_Small]  (no BOM)
Logo3  FCC disclaimer  [FCC_disclaimer]  (no BOM)
Logo4  WEEE logo  [WEEE_Minimum]  (no BOM)
LOGO5  DANGER HIGH VOLTAGE  [IEC_HighVoltage_Small]  (no BOM)
LOGO6  DANGER HIGH VOLTAGE  [IEC_HighVoltage_Small]  (no BOM)
LOGO7  DANGER HIGH VOLTAGE  [IEC_HighVoltage_Small]  (no BOM)
LOGO8  DANGER HIGH VOLTAGE  [IEC_HighVoltage_Small]  (no BOM)
LOGO9  CAUTION HOT SURFACE  [IEC_HotSurface_Small]  (value not drawn)  (no BOM)
LOGO10  CAUTION.  READ USER GUIDE BEFORE USE  [IEC_Caution_Small]  (value not drawn)  (no BOM)
ZZ1  This Assembly Note is for PCB labels only  [AssemblyNoteLabel]  (no BOM)
ZZ2  These assemblies are ESD sensitive, ESD precautions shall be observed.  [AssemblyNote]  (no BOM)
ZZ3  These assemblies must be clean and free from flux and all contaminants. Use of no clean flux is not acceptable.  [AssemblyNote]  (no BOM)
ZZ4  These assemblies must comply with workmanship standards IPC-A-610 Class 2, unless otherwise specified.  [AssemblyNote]  (no BOM)

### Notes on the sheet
- Variant
- Variant/Label Table
- Label Text
- You should delete the nylon screws/standoffs and/or the bumpons as needed for your design (or substitute other parts from Hardware.IntLib).  Bumpons are cheaper, but provide less clearance.
  Deleting anything else from this page may result in your EVM submission being rejected (until you add them back).
  Update the Label Text in the Label Table as needed for each Assembly Variant.
  You should delete this note too.
- 001
- 002
- TPSI31XXQ1EVM
- ChangeMe!

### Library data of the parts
!PCB1 = CMP-0003618-2: Manufacturer: Any; PartNumber: LP111
FID1-FID3 = CMP-0077181-1: Fiducial mark.  There is nothing to buy or mount.
H1-H16 = CMP-0003620-1: Bumpon, Hemisphere, 0.44 X 0.20, Clear; Manufacturer: 3M
Logo1 = CMP-0074844-1: SymbolCreator: a0412235
Logo2 = CMP-0074838-1: Texas Instrument Corporate Signature; SymbolCreator: a0412235; Lib Reference: TI_Logo; Library Reference: Logo
Logo3 = CMP-0074847-1: FCC_disclaimer; Library Reference: Logo
Logo4 = CMP-0074769-1
LOGO5-LOGO8 = CMP-0074835-1: IEC 61010-1 High Voltage Warning; SymbolCreator: a0412235
LOGO9 = CMP-0074837-2: IEC 61010-1 Hot Surface Warning; Manufacturer: Texas Instruments; CompType: IC; AEC Category: Q200; SymbolCreator: a0412235
LOGO10 = CMP-0074836-1: IEC 61010-1 Caution Warning; SymbolCreator: a0412235; Lib Reference: IEC_Caution
ZZ1 = CMP-0003616-3
ZZ2 = CMP-0077236-1
ZZ3 = CMP-0077237-1
ZZ4 = CMP-0077238-1

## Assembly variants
001: not fitted FID1 FID2 FID3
